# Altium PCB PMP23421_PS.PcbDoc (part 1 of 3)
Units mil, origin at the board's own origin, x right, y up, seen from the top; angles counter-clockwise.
Board outline 1978.53 x 2528.22 mil, 6 copper layers (Top Layer, Signal Layer 1, Signal Layer 2, Signal Layer 3, Signal Layer 4, Bottom Layer), stack 61.3 mil thick; 156 components, 45 nets, 410 pads, 635 vias.
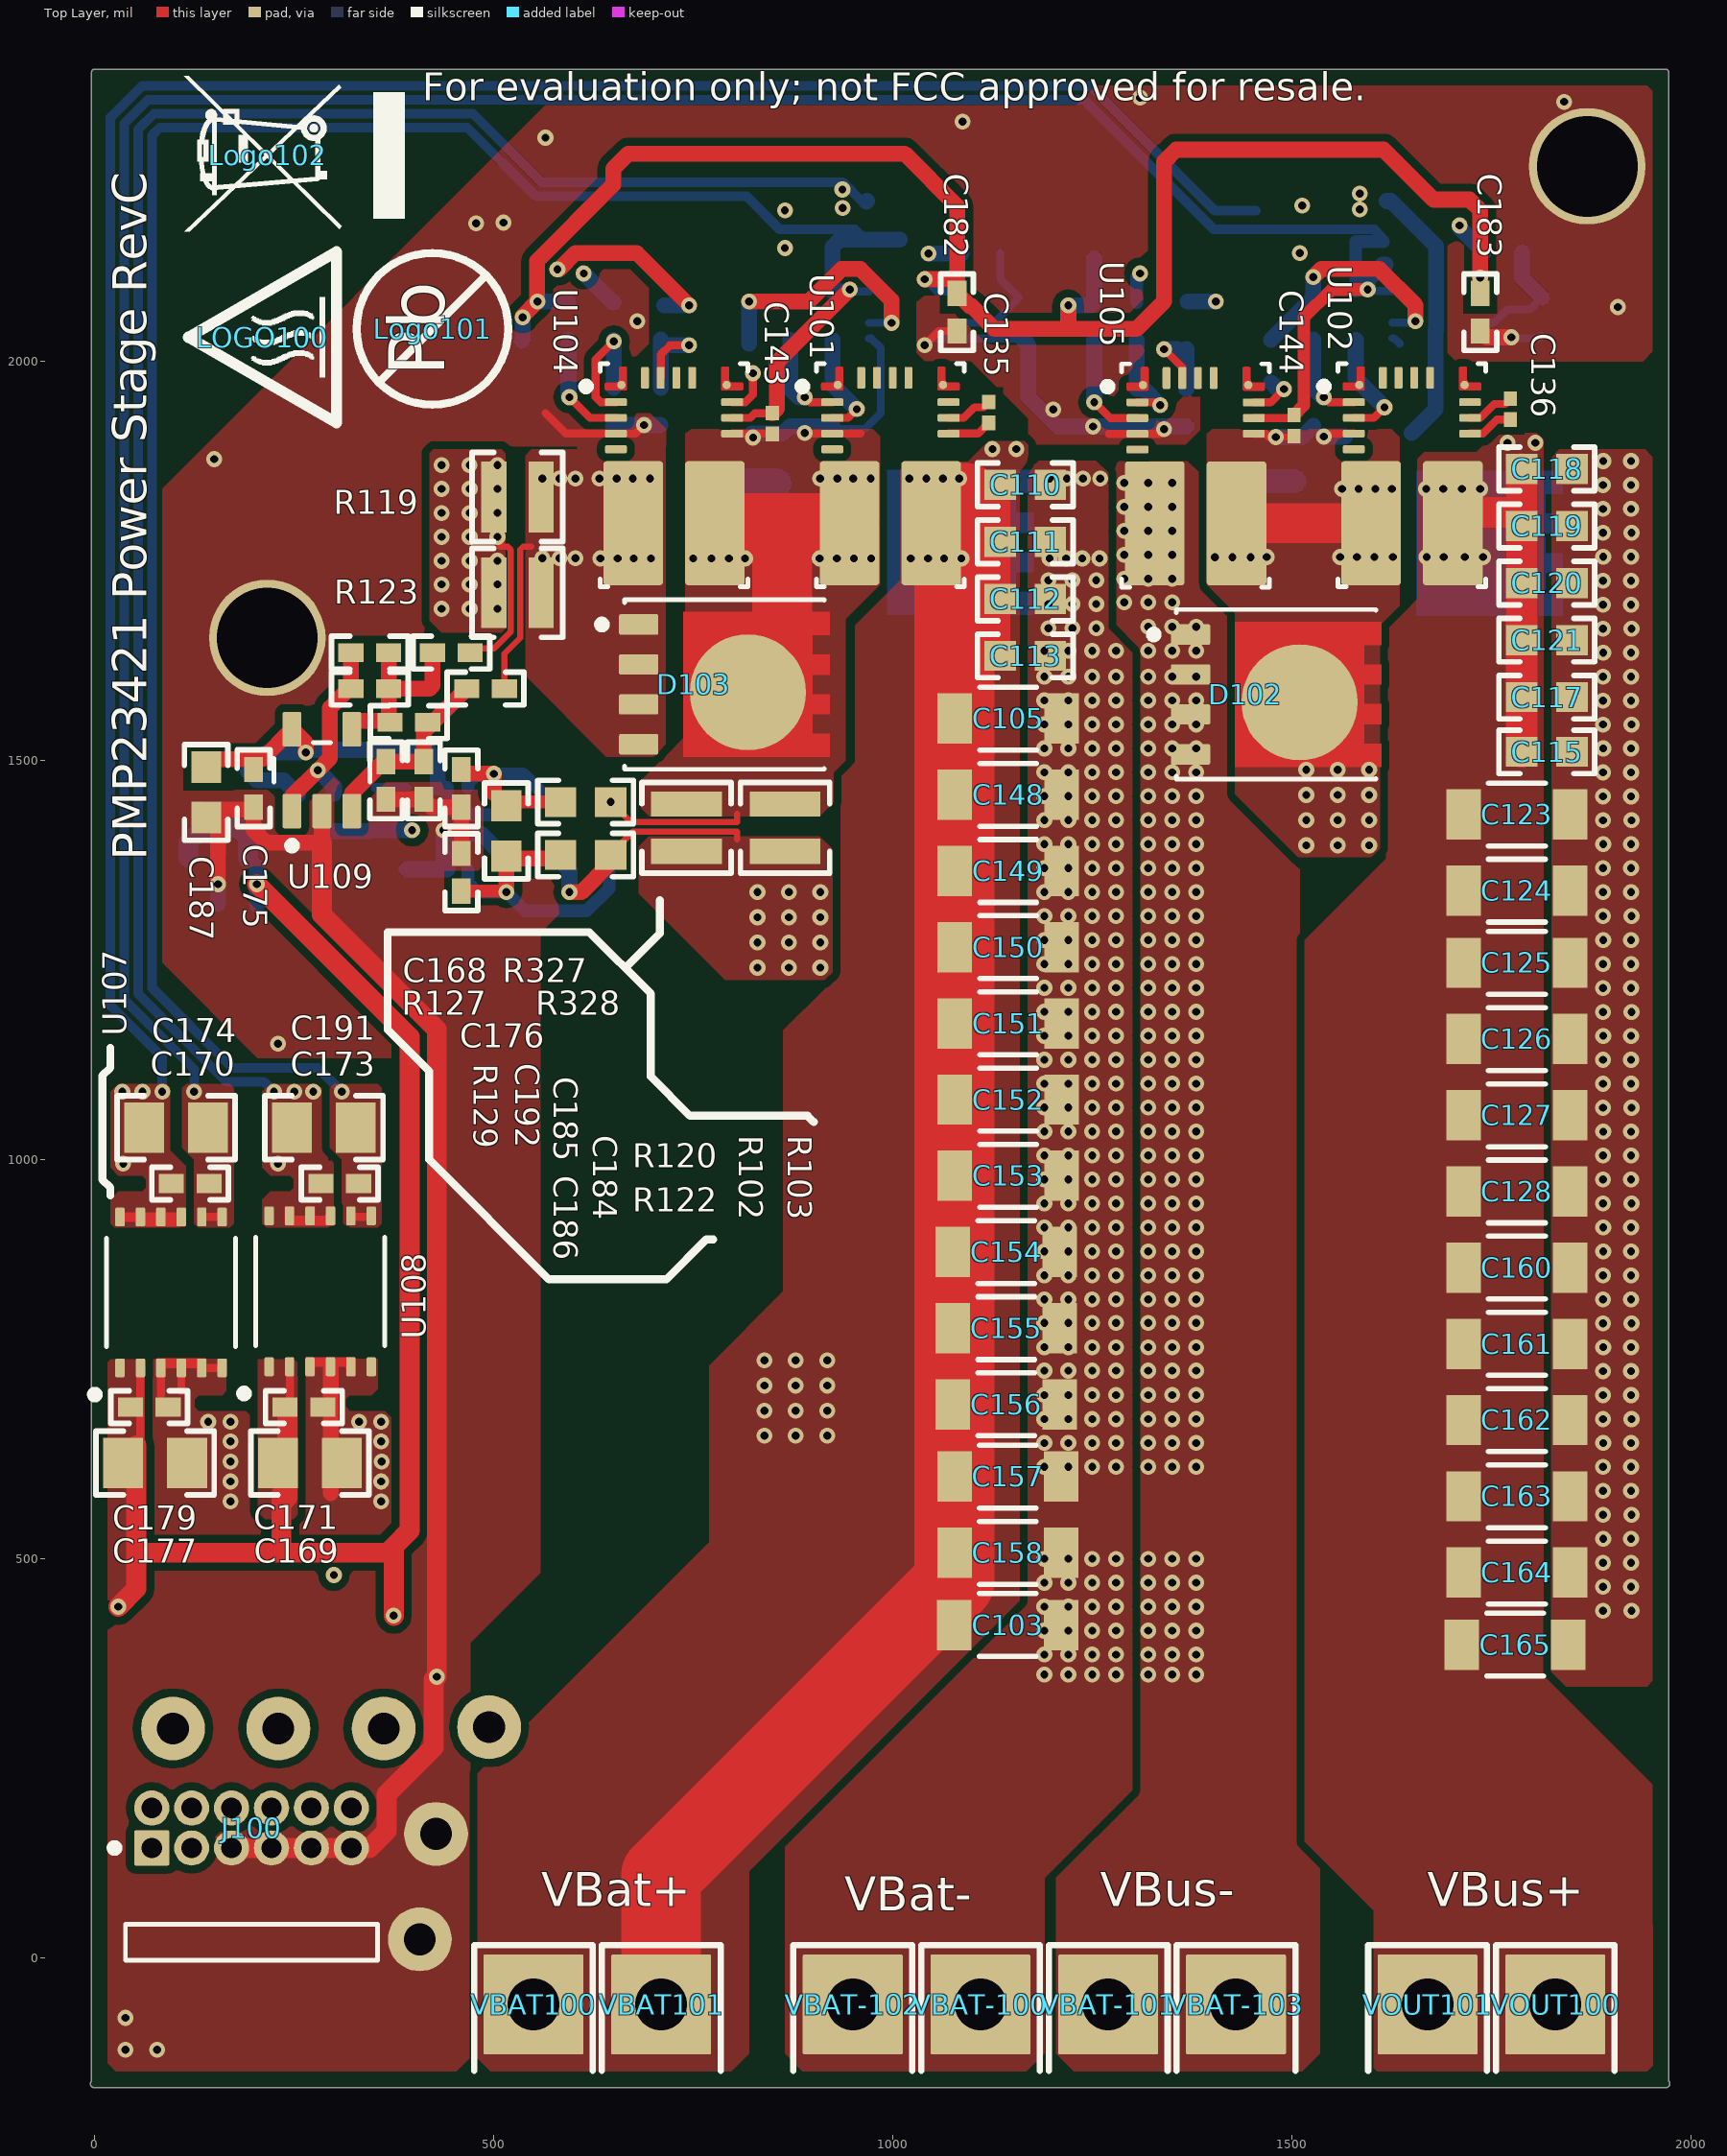
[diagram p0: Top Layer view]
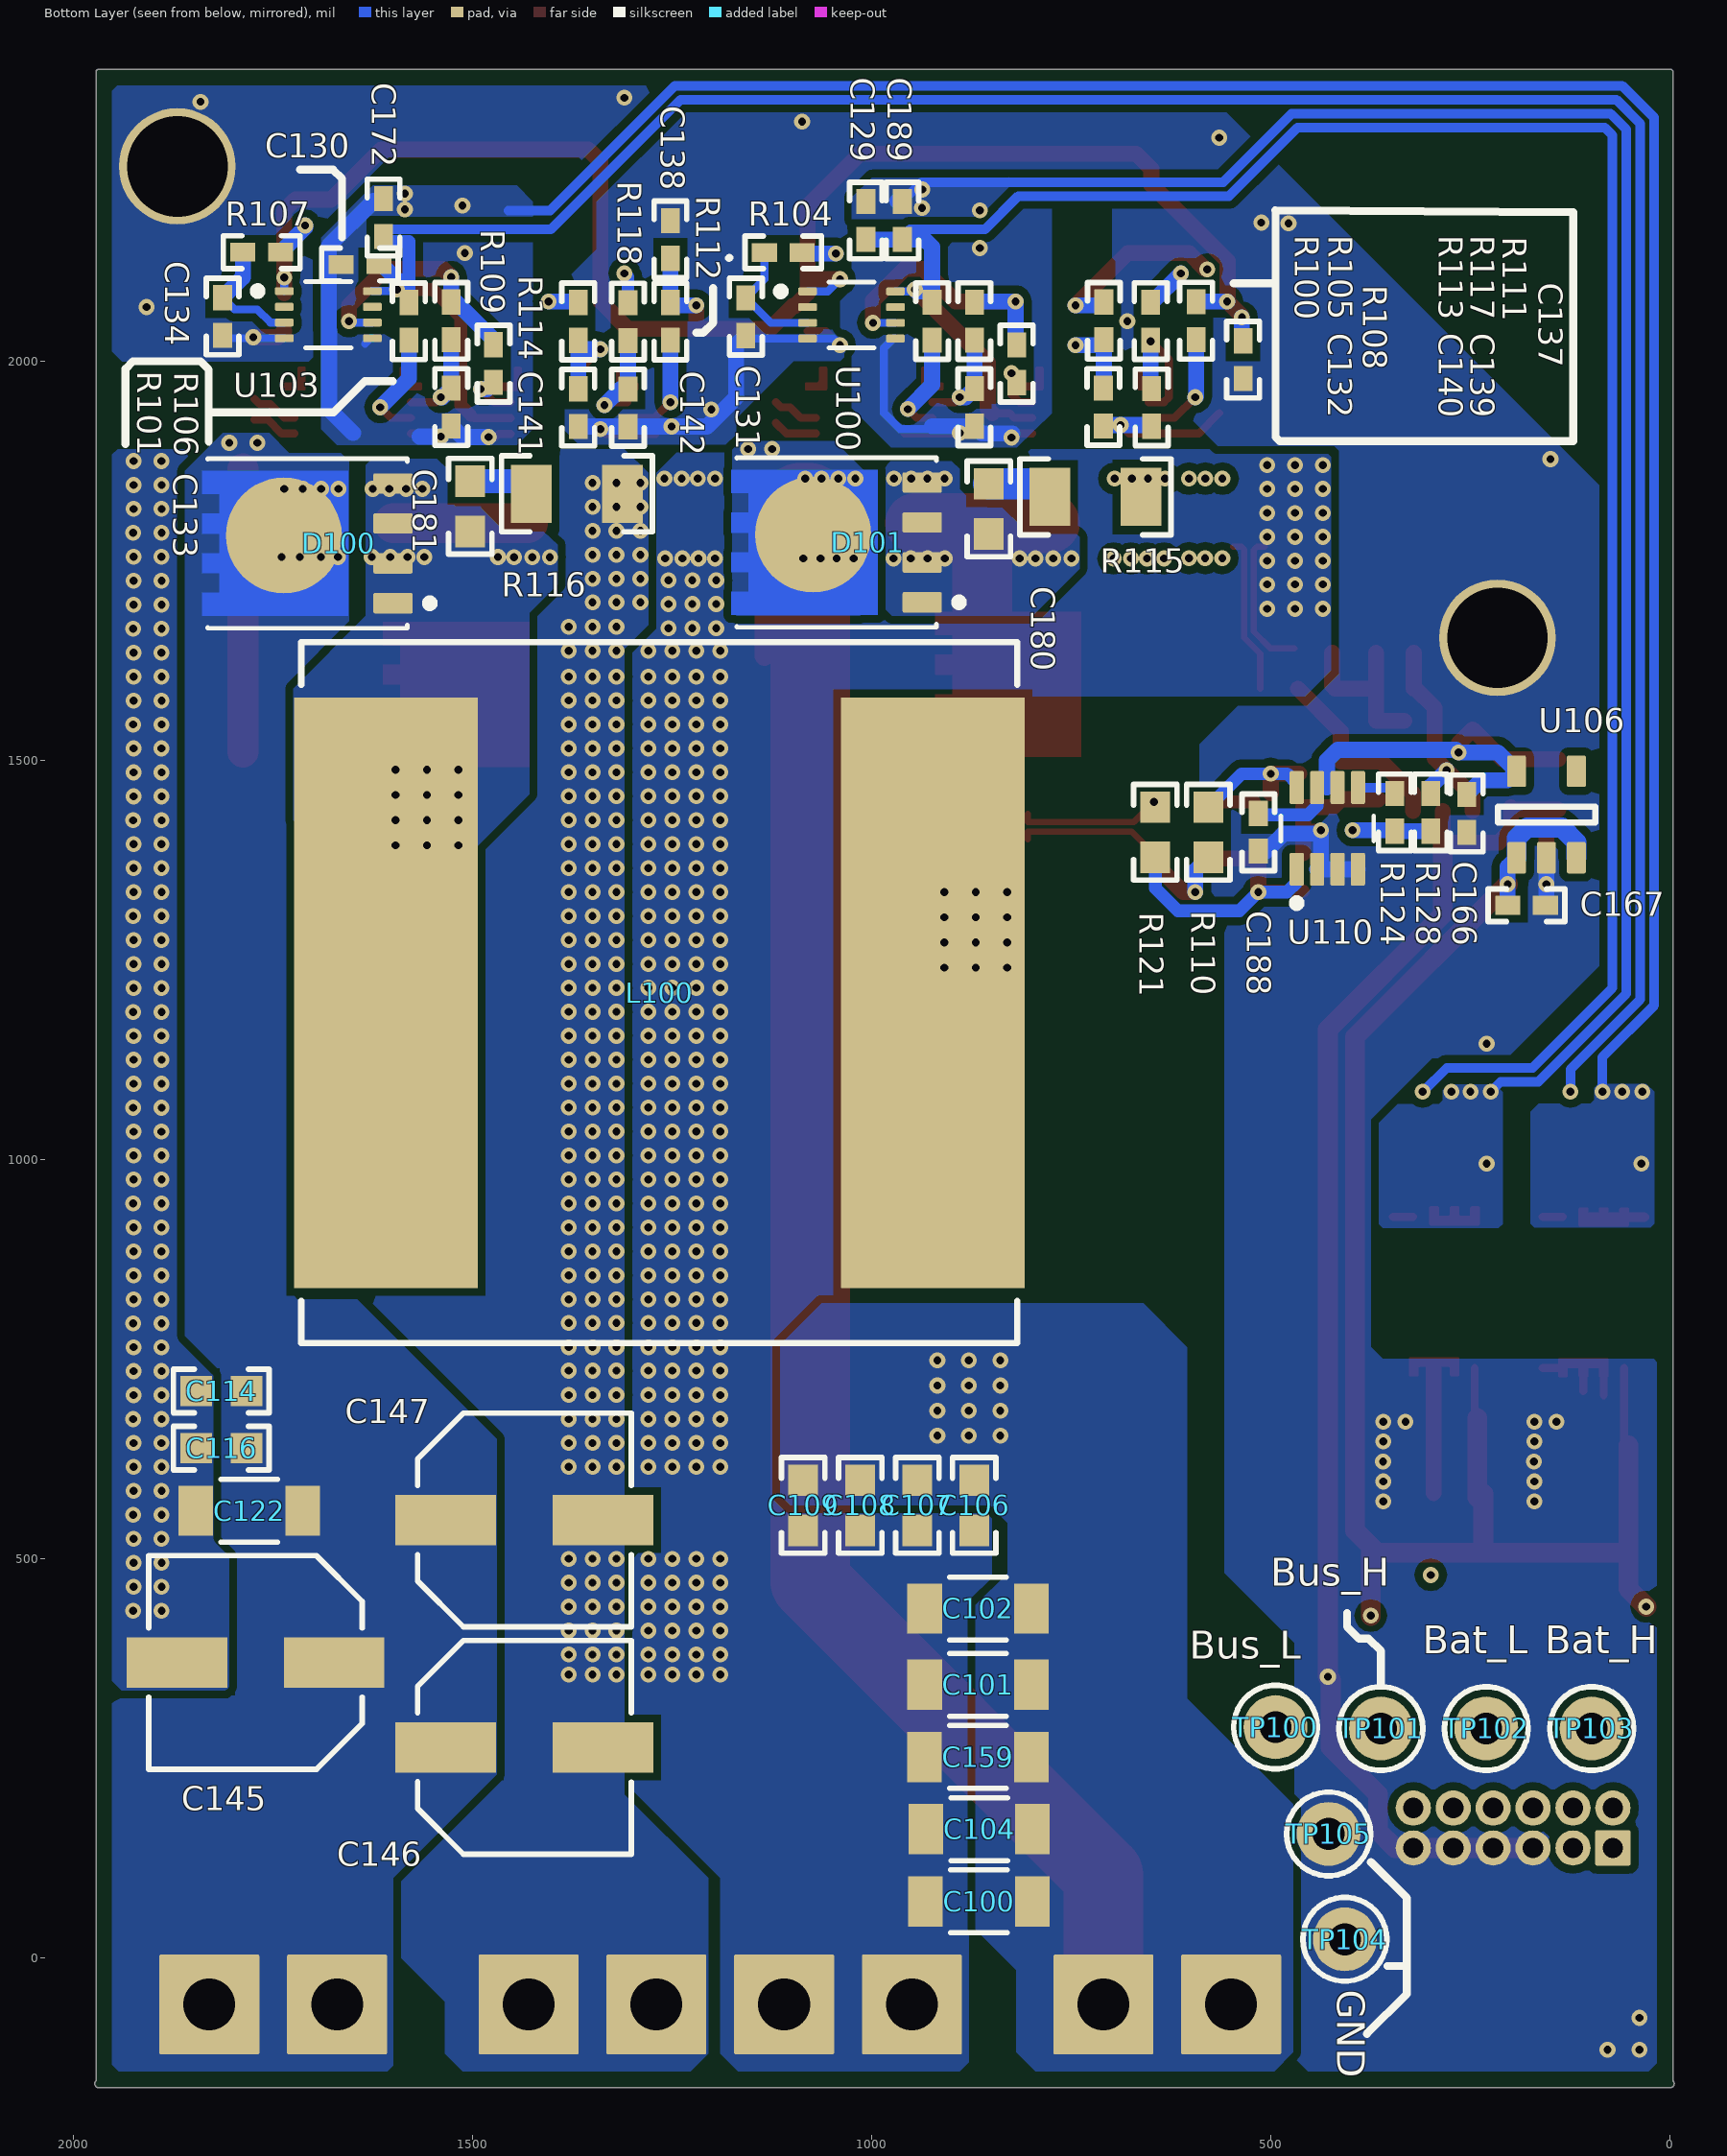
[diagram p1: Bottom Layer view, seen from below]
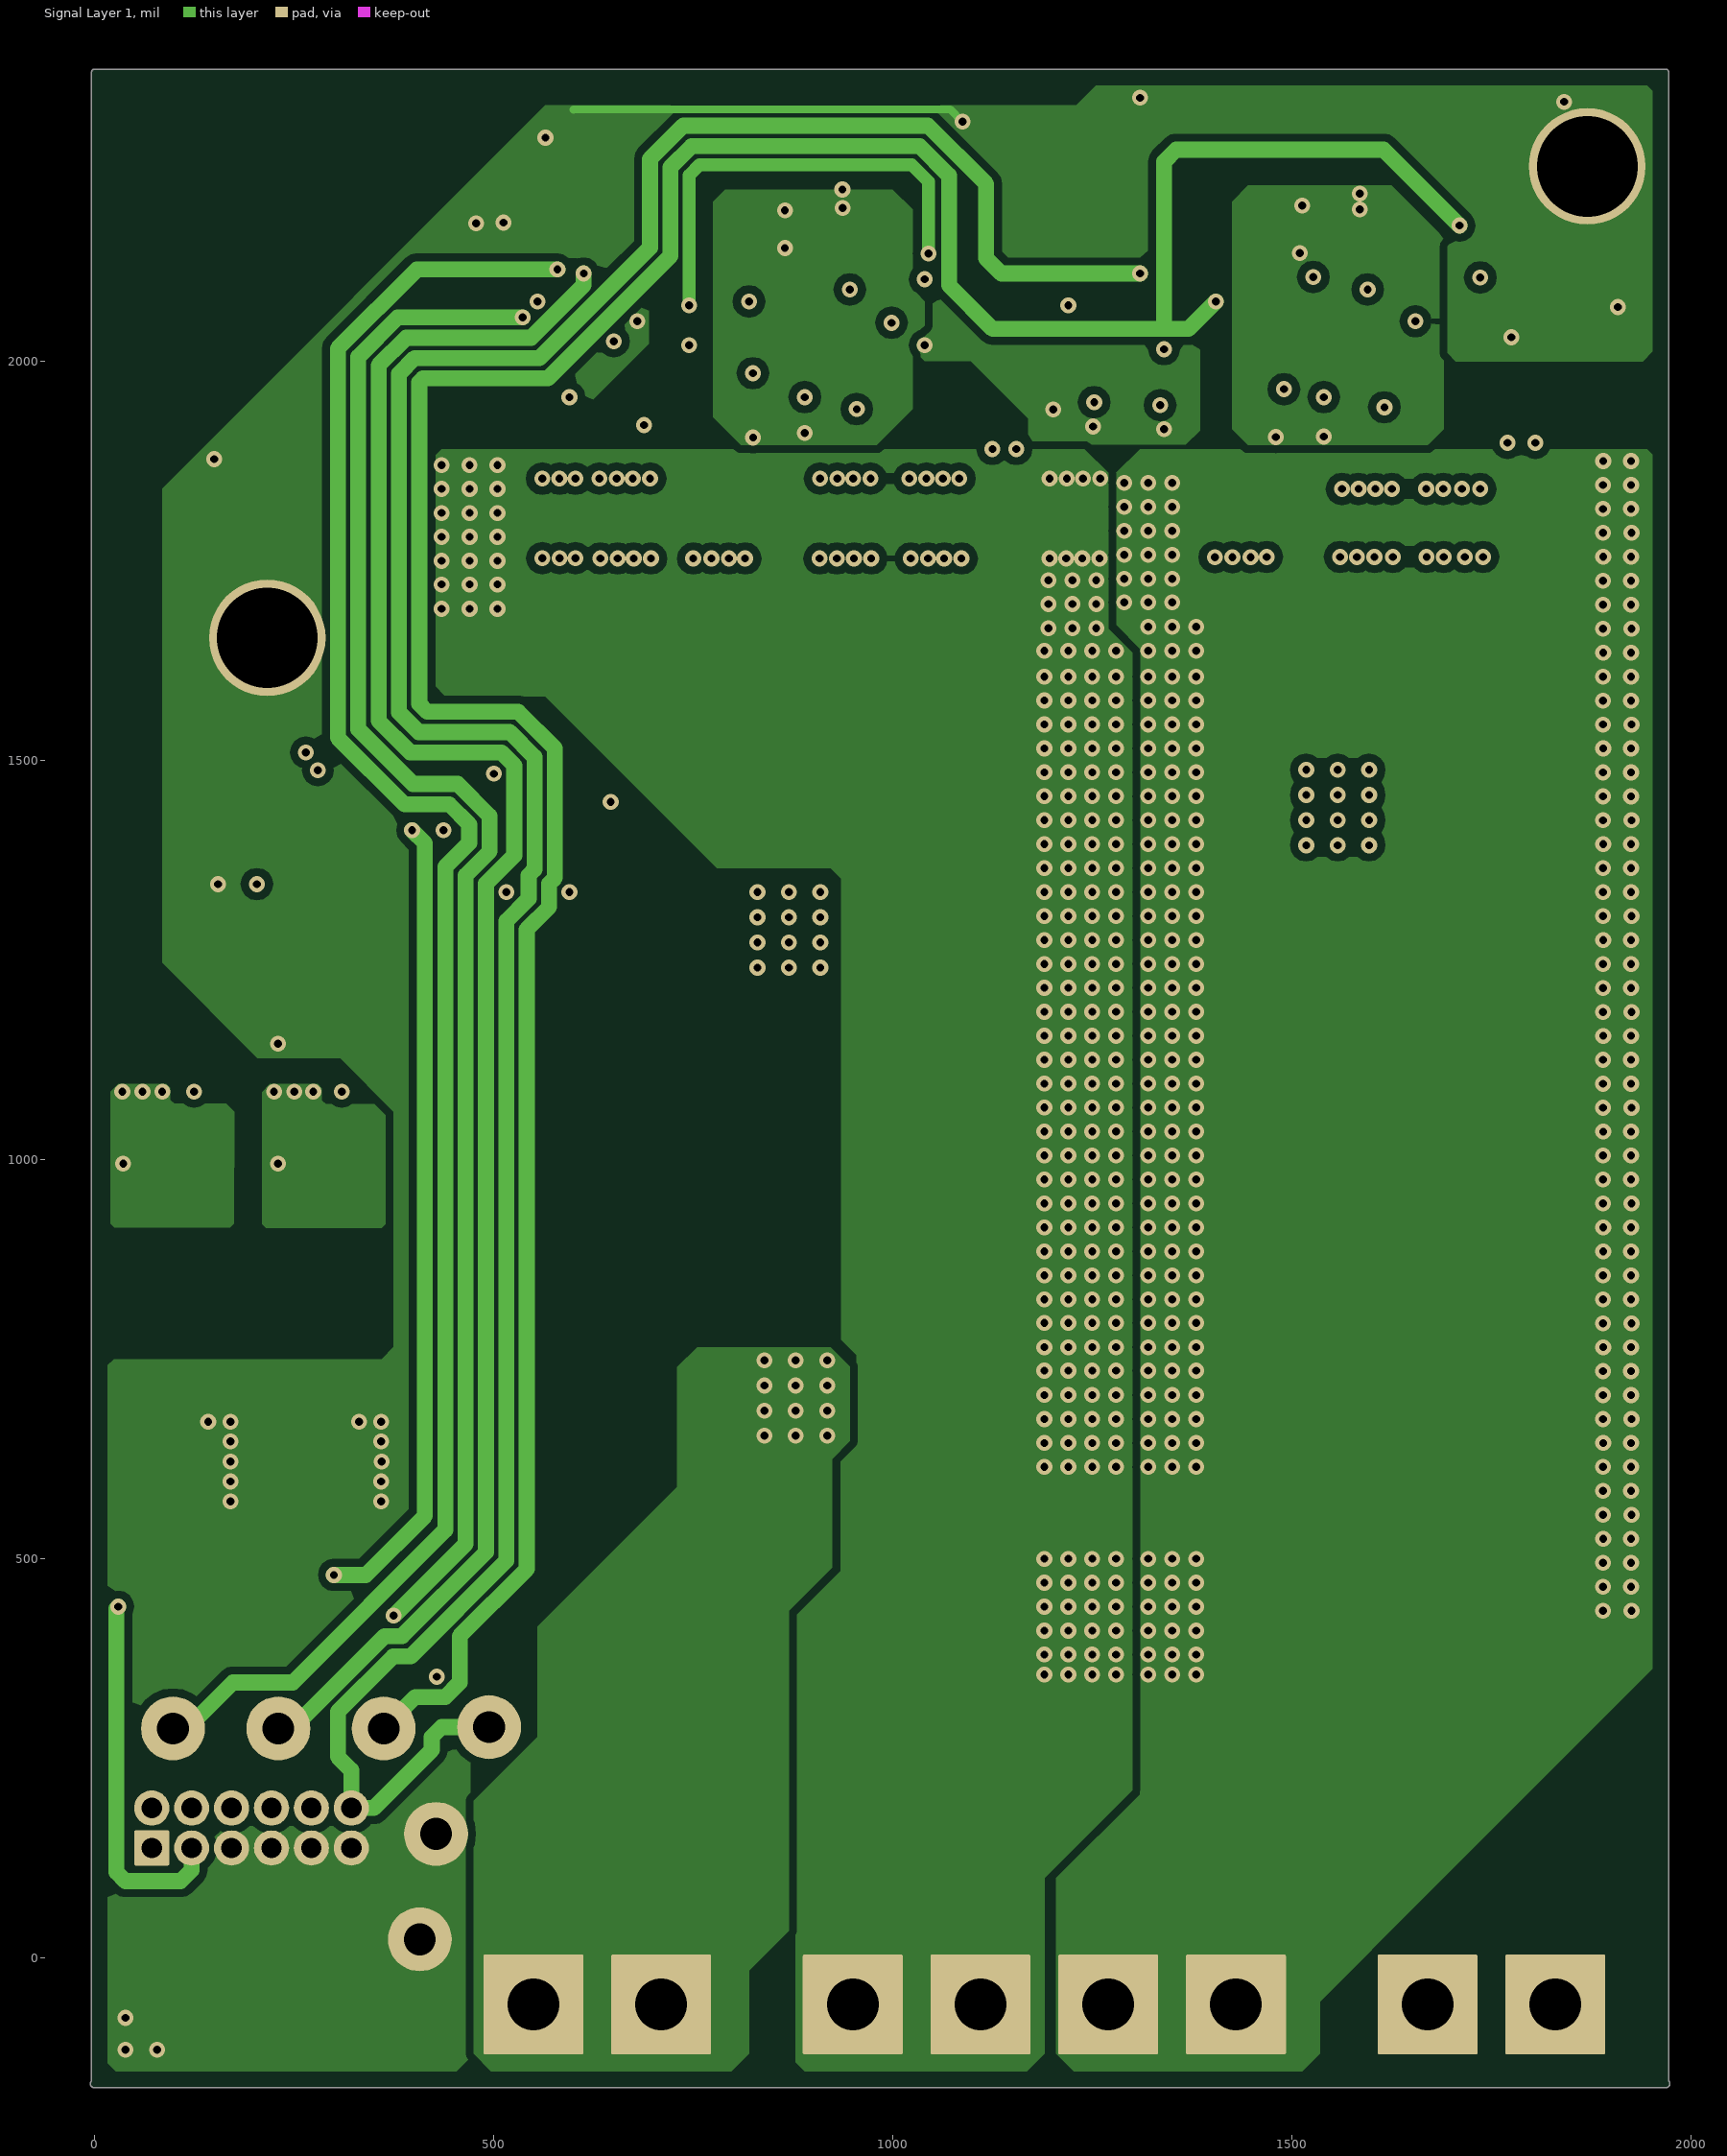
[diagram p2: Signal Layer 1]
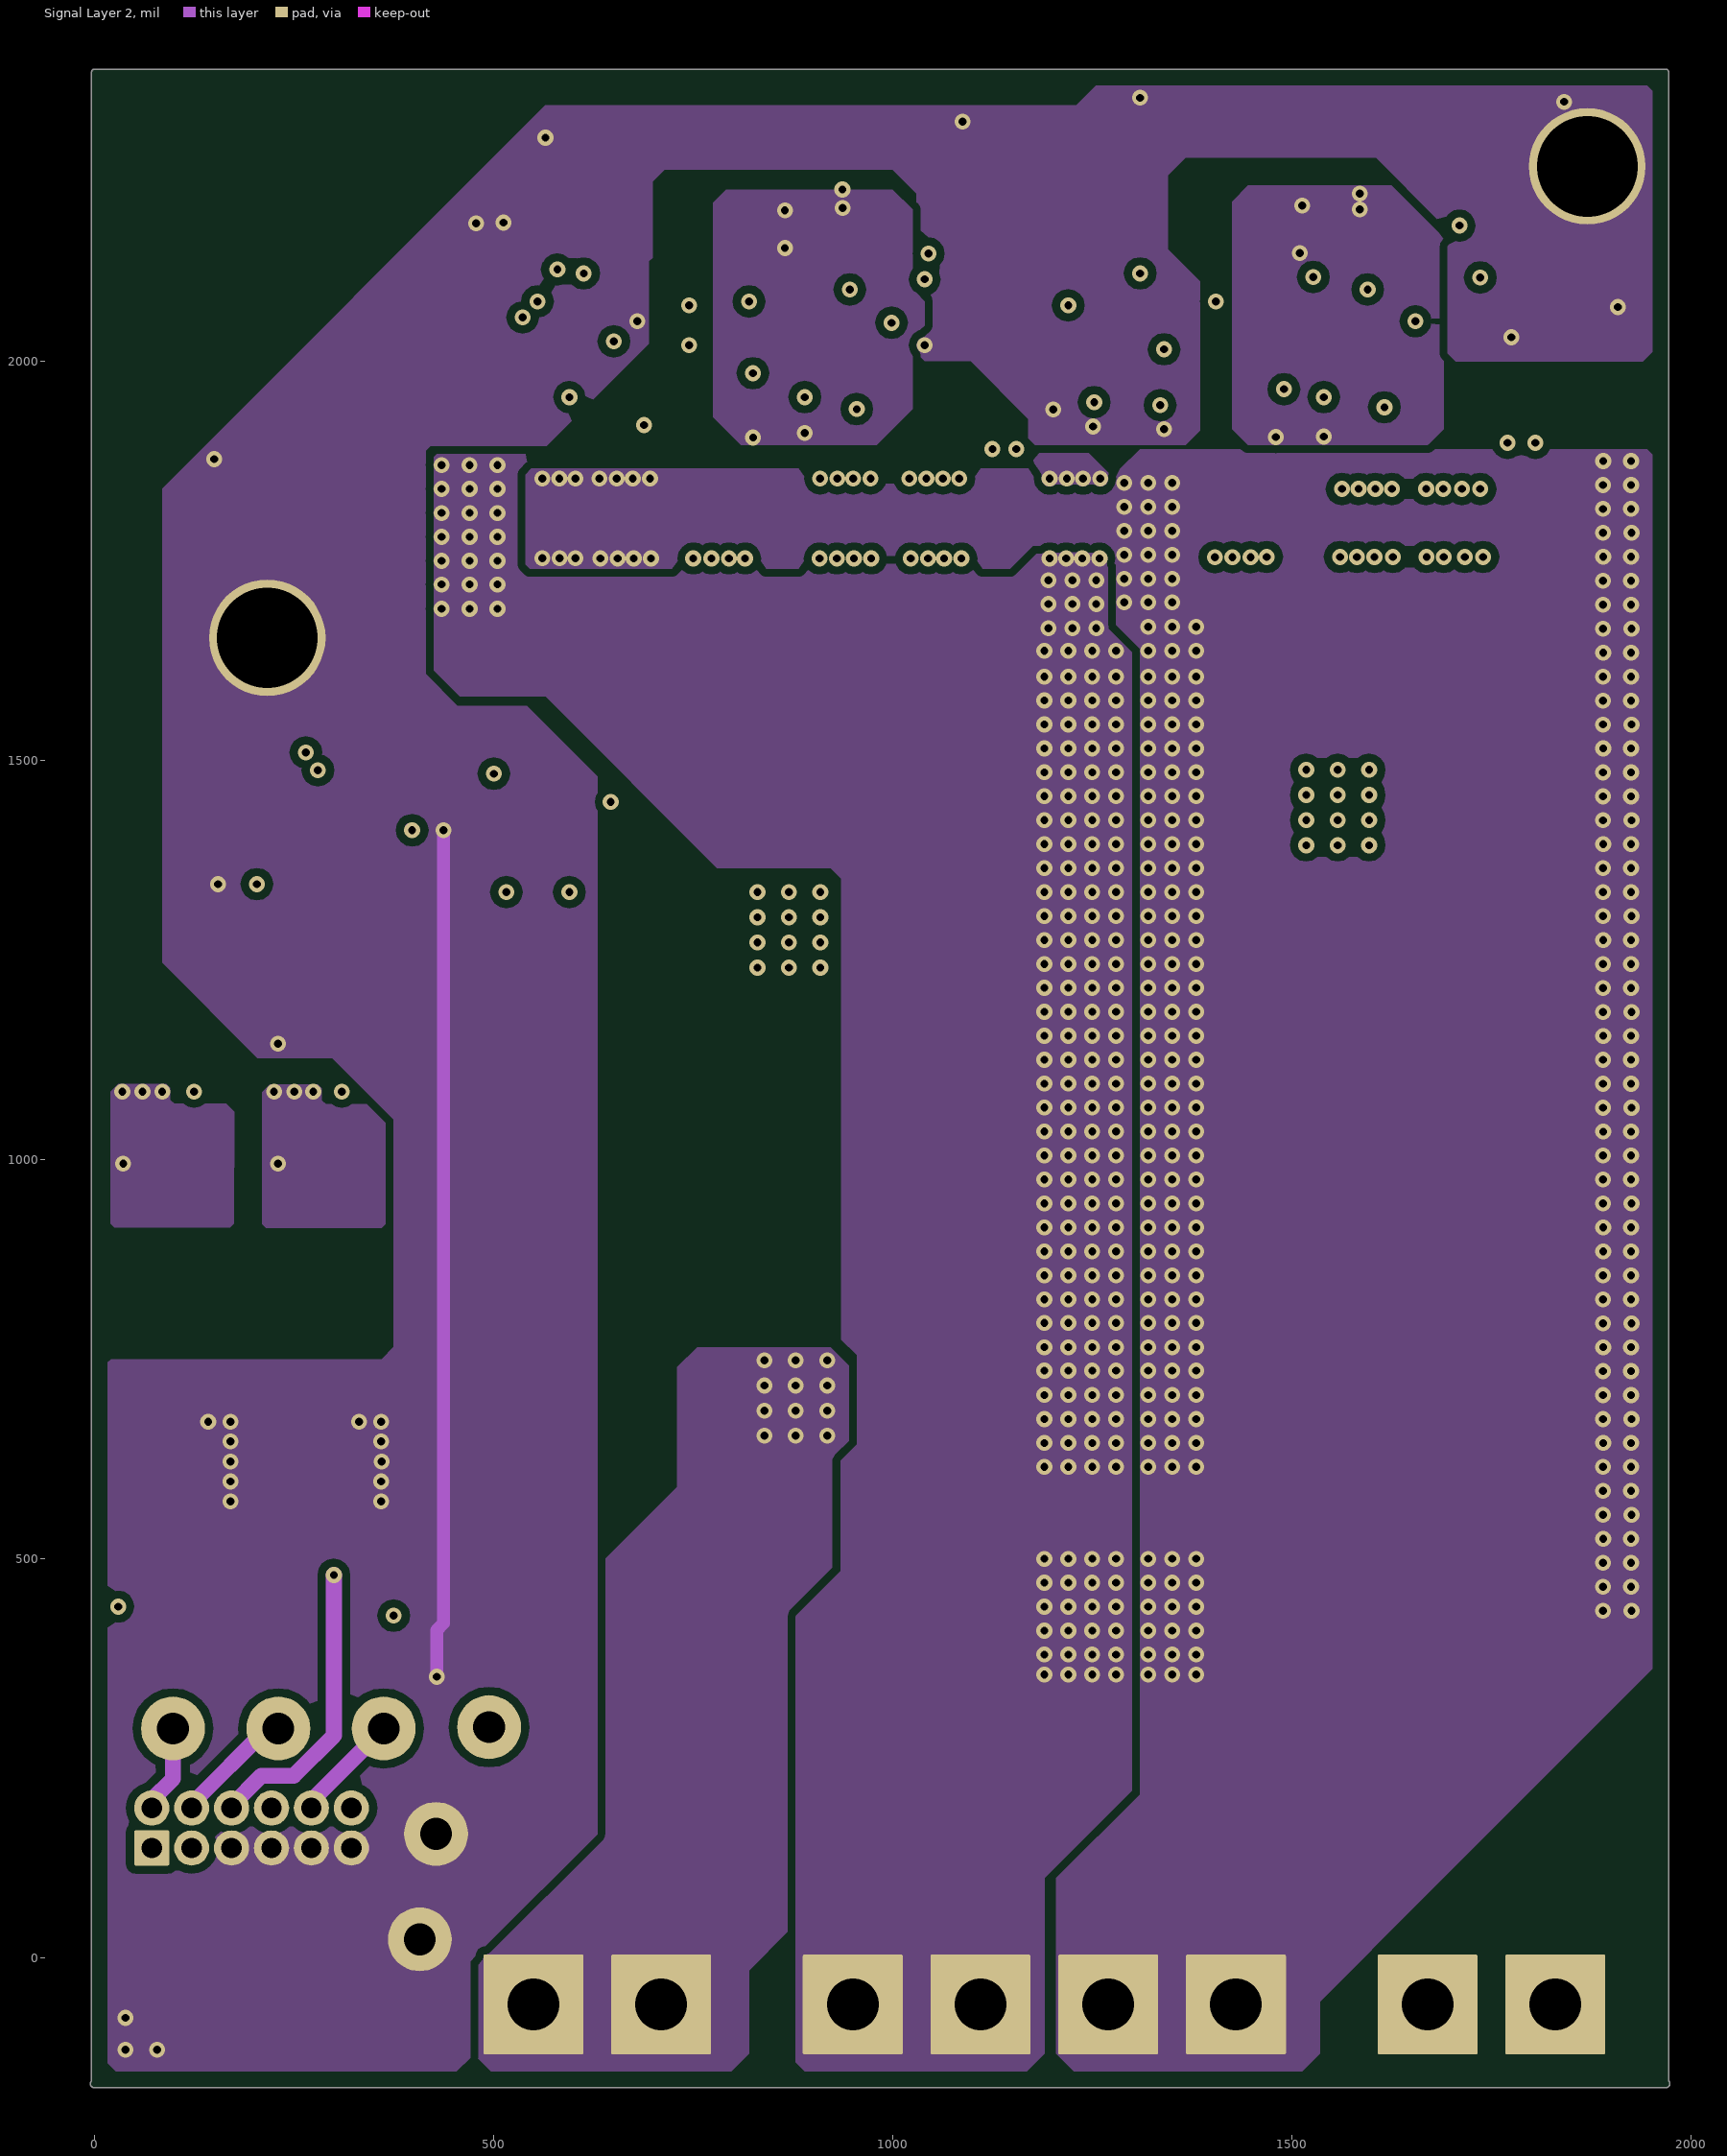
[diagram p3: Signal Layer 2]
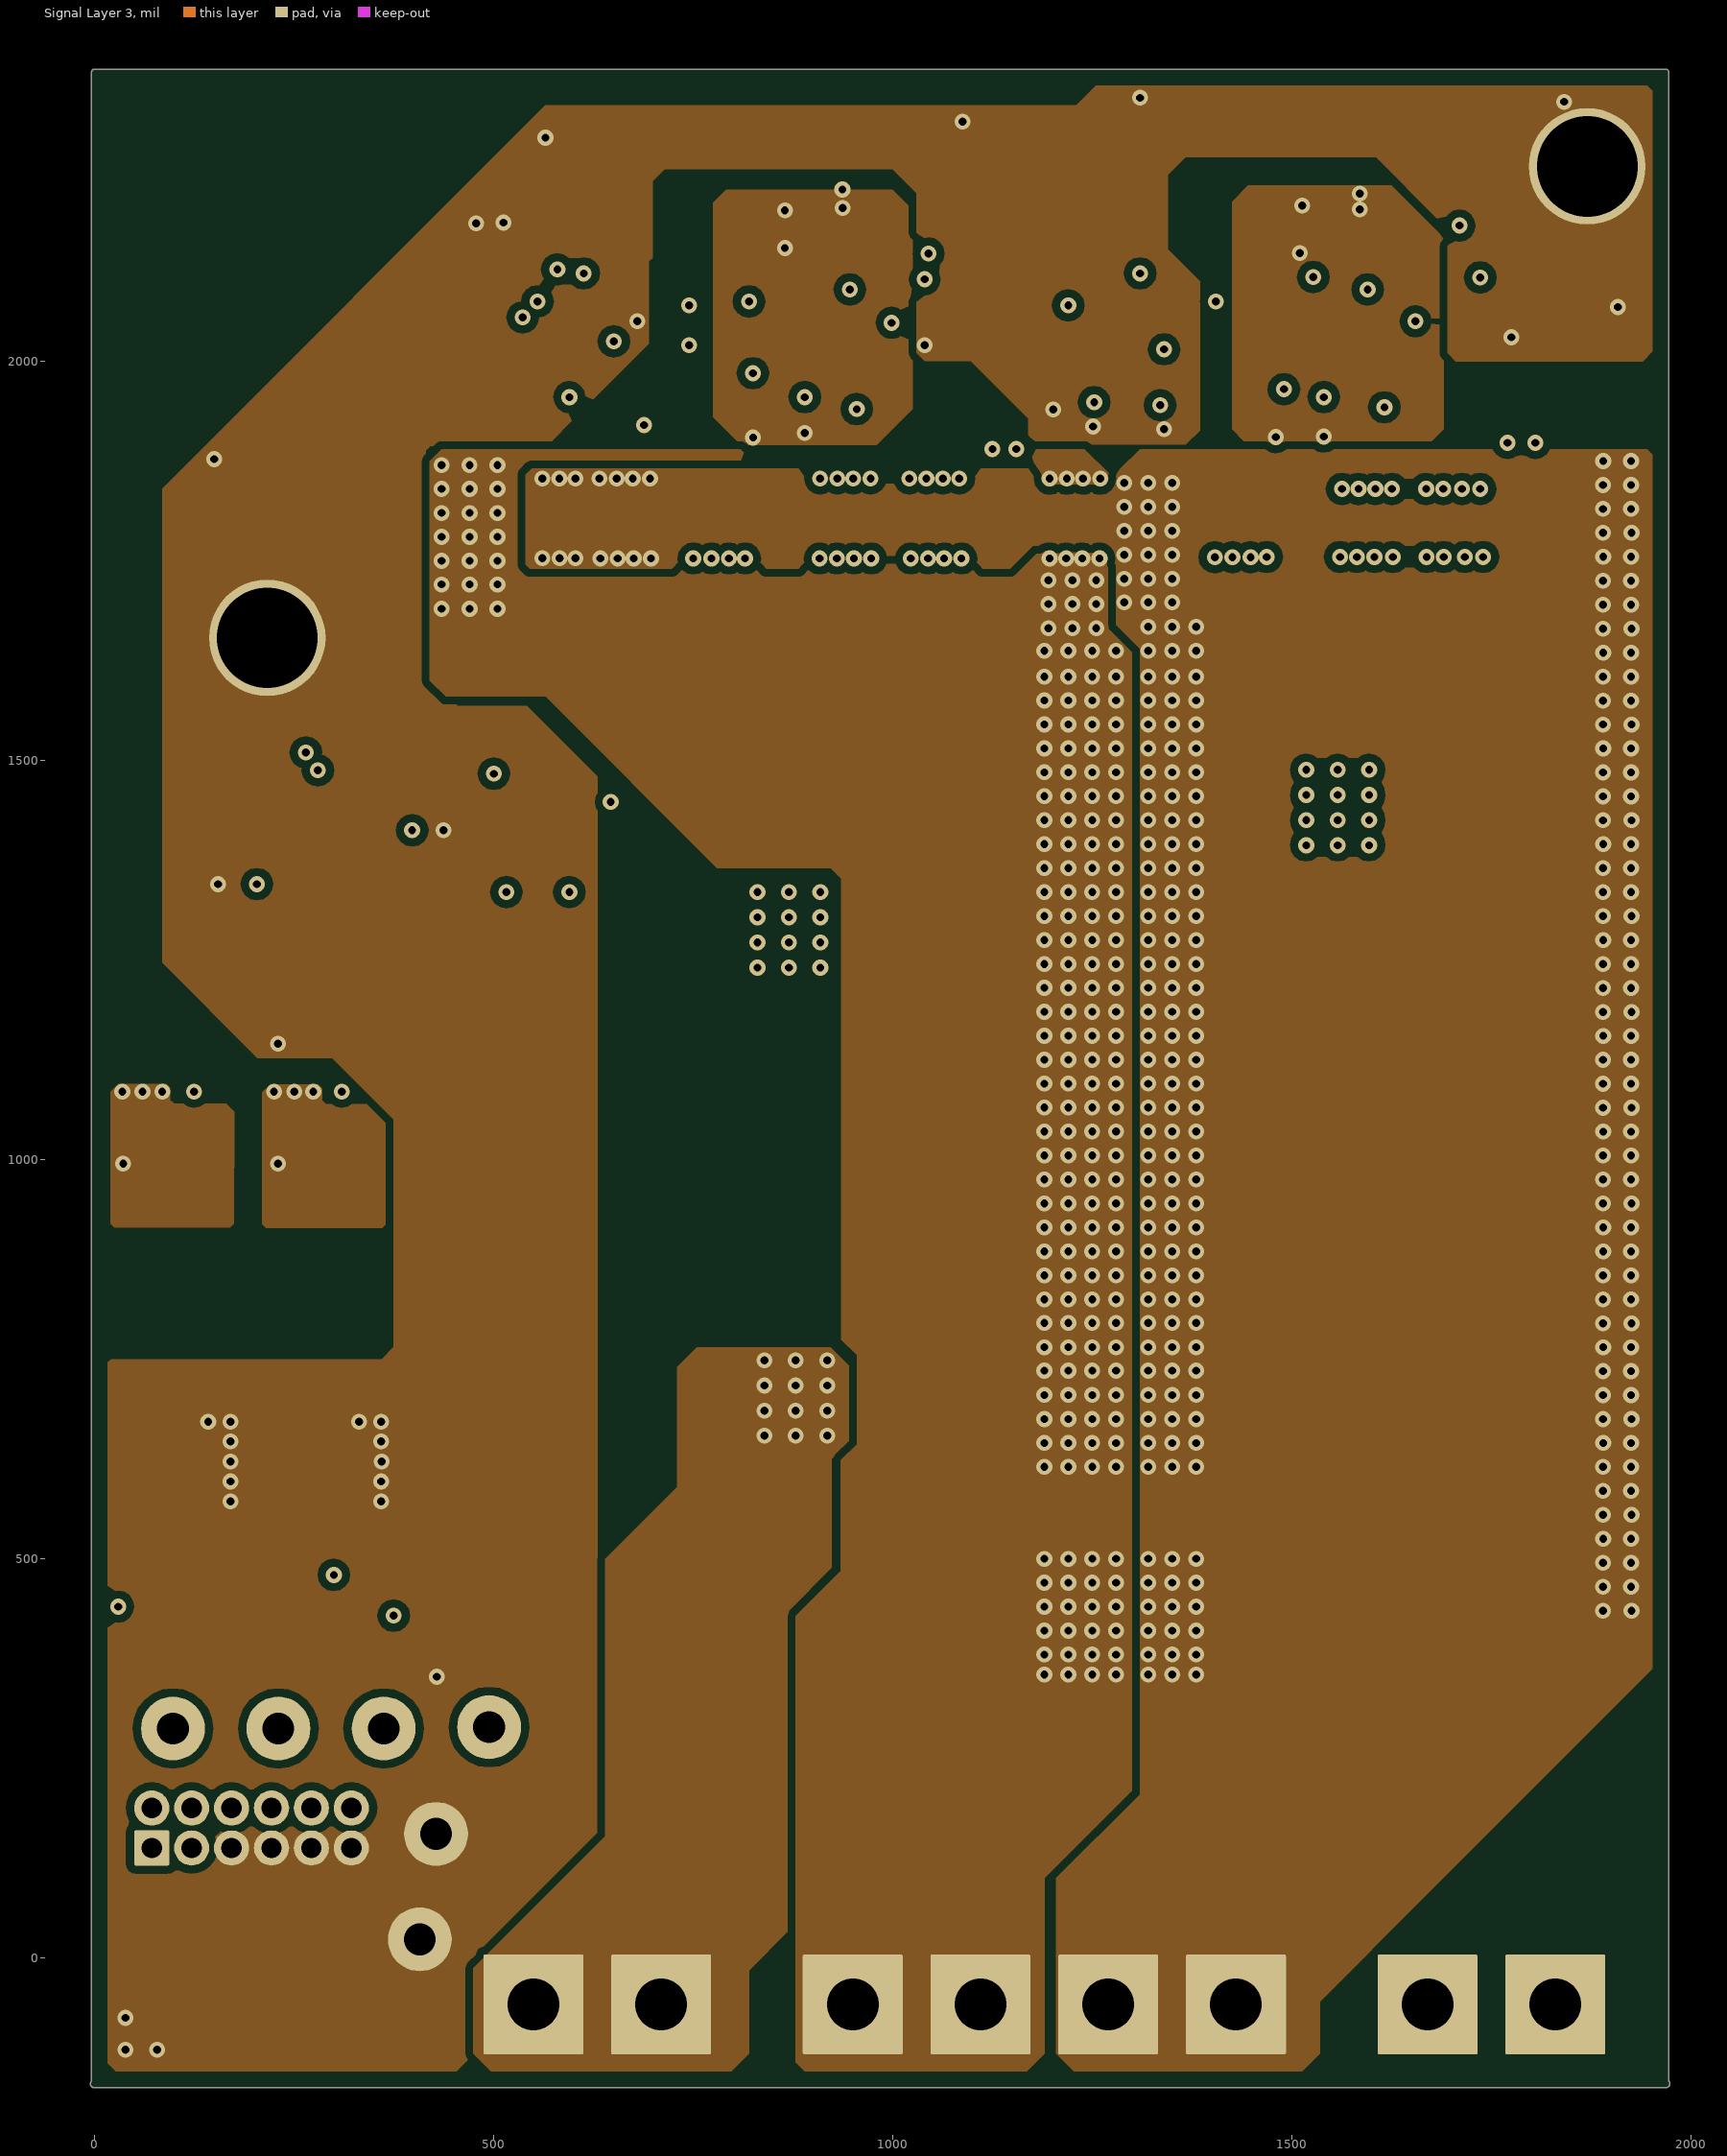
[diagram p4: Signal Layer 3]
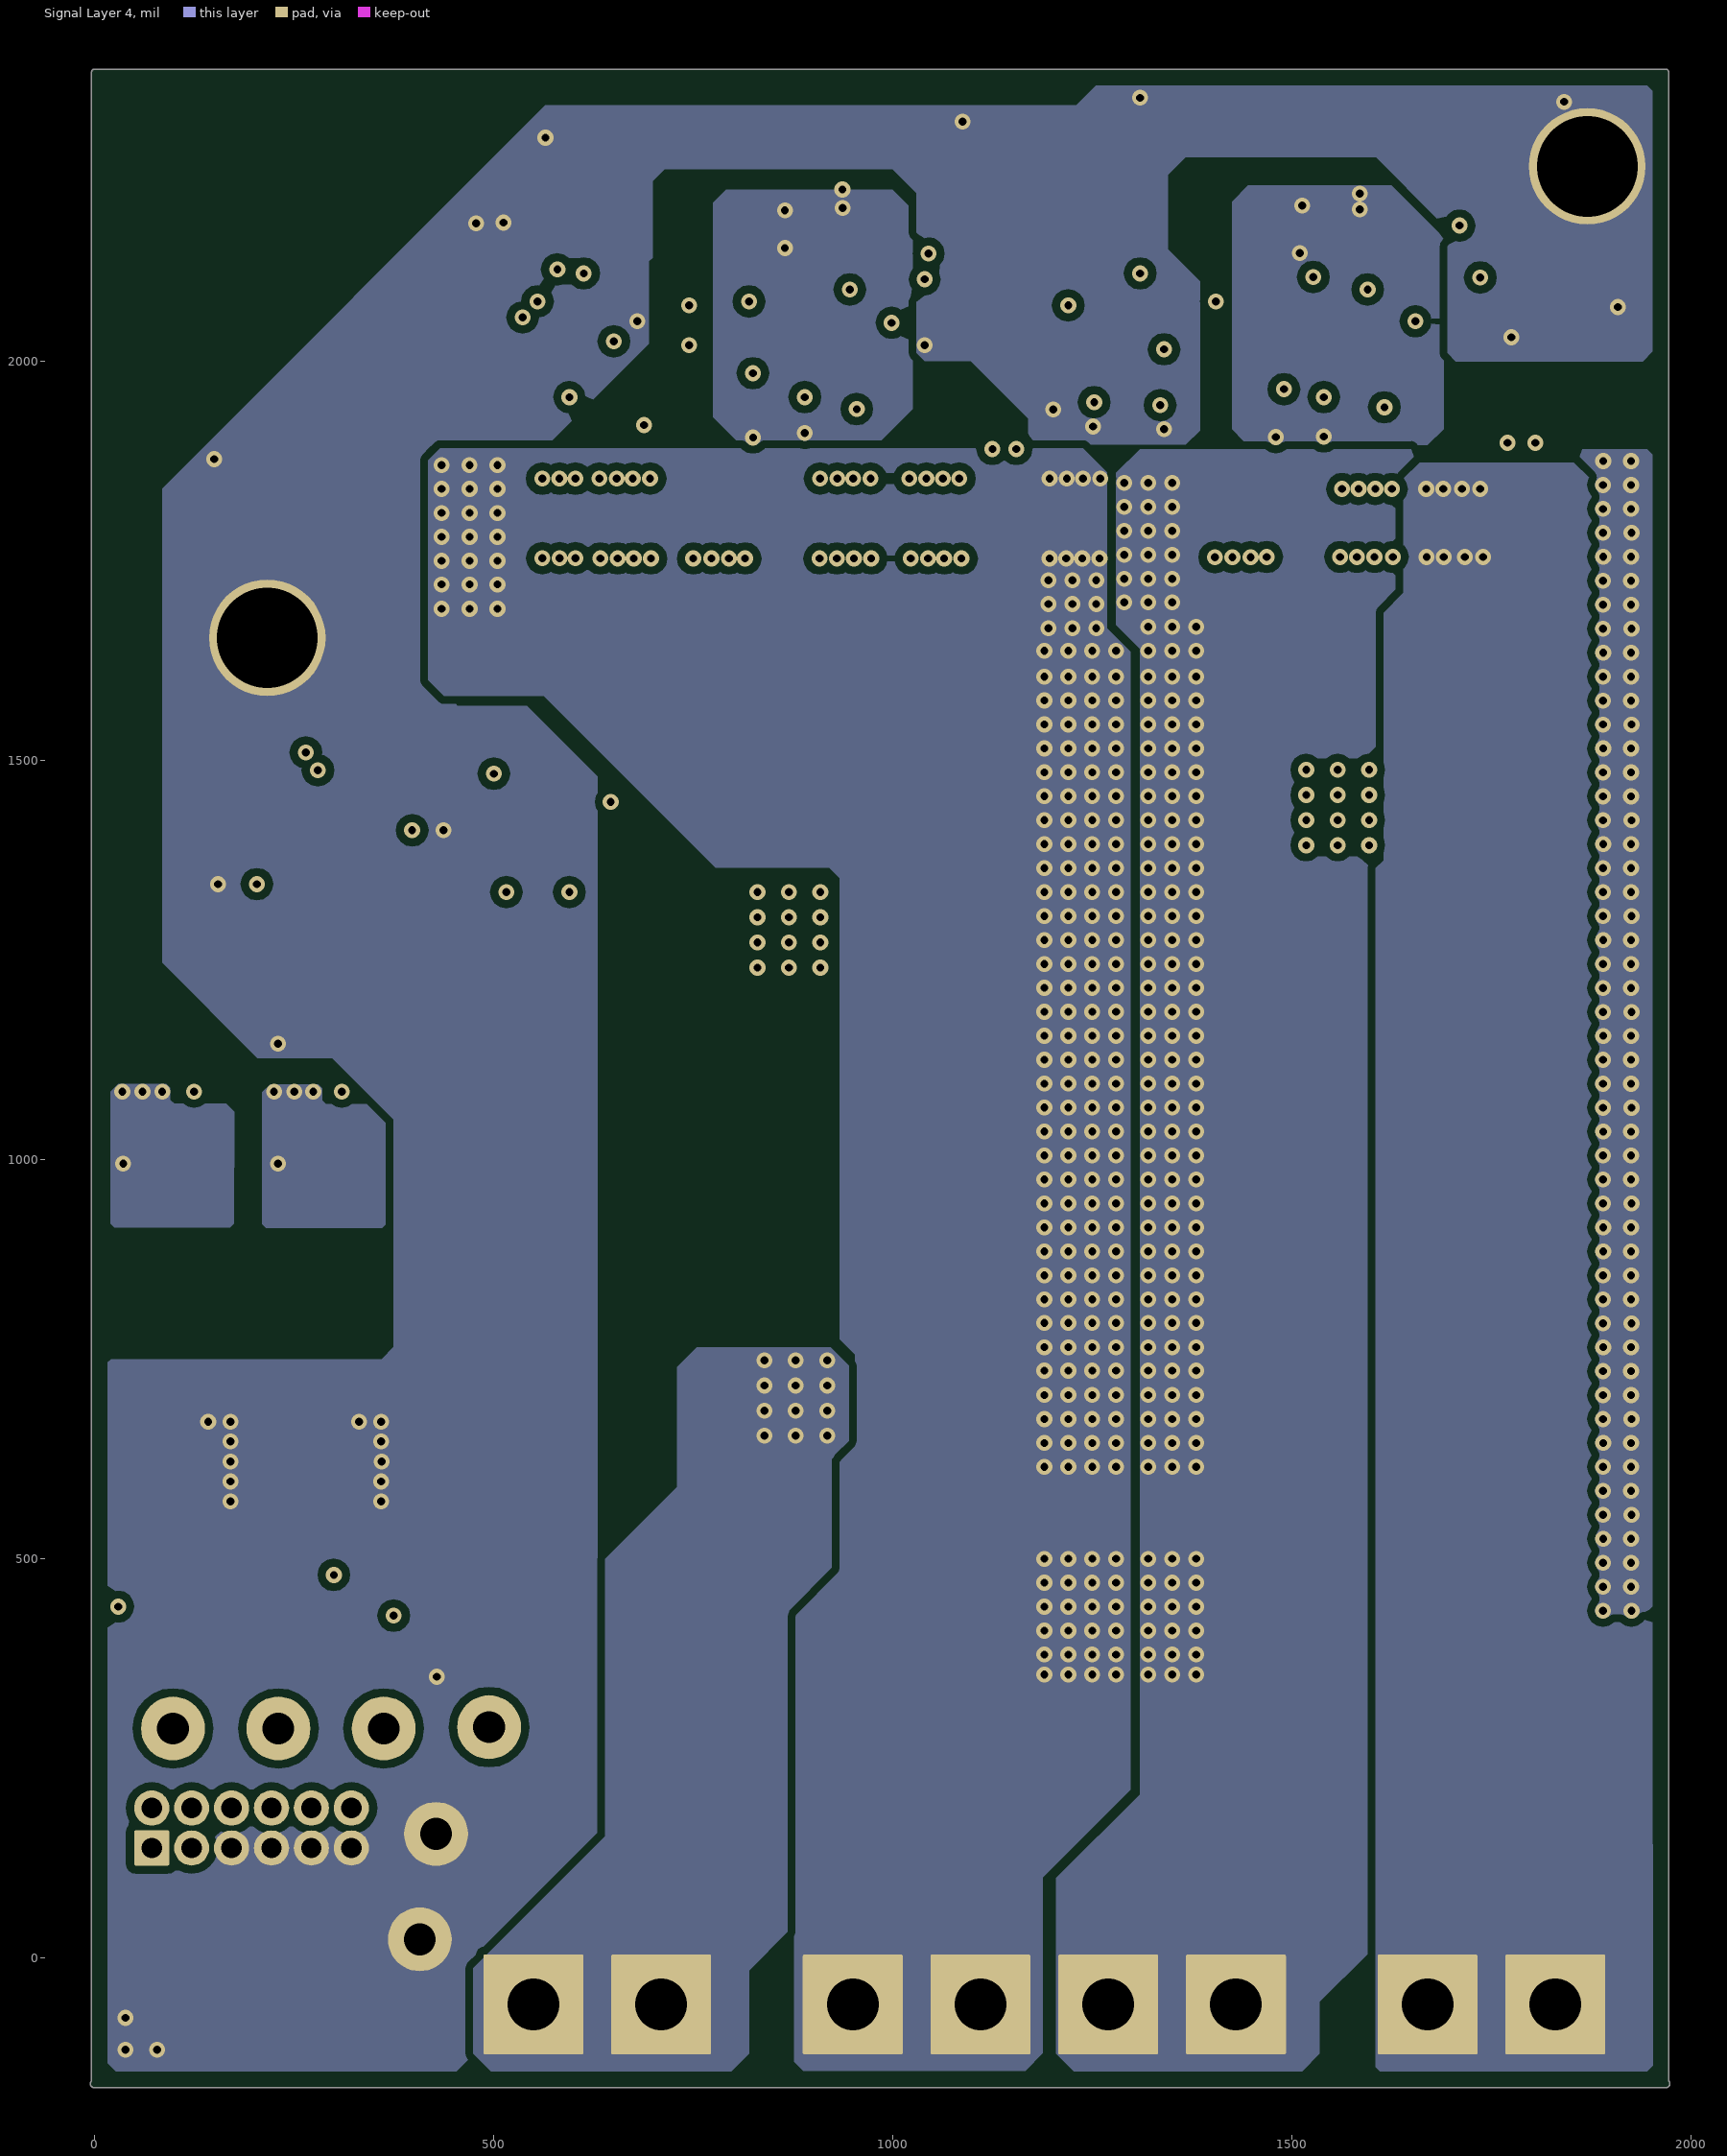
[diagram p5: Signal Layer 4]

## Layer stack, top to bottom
Top Solder: solder mask 0.394, Solder Resist, Dk 3.5
Top Layer: signal copper 2.8
Dielectric 2: prepreg 5.5, FR-4, Dk 4.2
Signal Layer 1: signal copper 2.8
Dielectric1: core 14, FR-4, Dk 4.2
Signal Layer 2: signal copper 2.8
Dielectric 3: prepreg 5.5, FR-4, Dk 4.2
Signal Layer 3: signal copper 2.8
Dielectric 4: dielectric 14, FR-4, Dk 4.2
Signal Layer 4: signal copper 2.8
Dielectric 5: dielectric 5.5, FR-4, Dk 4.2
Bottom Layer: signal copper 2.8
Bottom Solder: solder mask 0.394, Solder Resist, Dk 3.5

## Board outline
0,-162.5 cw(c0,-157.48) -3.52,-153.91 -3.52,2362.2 cw(c0,2362.2) 0,2365.72 1968.5,2365.72 cw(c1968.5,2362.2) 1972.02,2362.2 1972.02,-153.91 cw(c1968.5,-157.48) 1973.52,-157.48 cw(c1968.5,-157.48) 1968.5,-162.5

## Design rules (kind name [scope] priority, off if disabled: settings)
AcuteAngle [All] p1: minimum=1.50000000000000E+0001 checktracksonly=FALSE
AssemblyTestPointUsage [All] p1: valid=2
BoardOutlineClearance BoardOutlineClearance_MountingHoles [OnCopper and InComponentClass('Mounting Holes')] p1: gap=40 ignorepadtopadclearanceinfootprint=FALSE
BoardOutlineClearance BoardOutlineClearance_Poly [OnCopper and IsPoly] p2: gap=20 ignorepadtopadclearanceinfootprint=FALSE
BoardOutlineClearance [OnCopper and Not InComponentClass('Logo') and not InComponentClass('FiducialMark') and not InRegion(1000,500,4000,800) and not InPoly] p3: gap=10 ignorepadtopadclearanceinfootprint=FALSE
Clearance Clearance_1 [InNetClass('HV') vs Not InNetClass('HV')] p1: gap=20 ignorepadtopadclearanceinfootprint=FALSE
Clearance Clearance_Keepouts [((IsTrack Or IsArc) And Not InPoly) And IsFree and IsKeepOut vs ((IsTrack Or IsArc) And Not InPoly) And IsFree and IsKeepOut] p2: gap=0 ignorepadtopadclearanceinfootprint=FALSE
Clearance Clearance_Poly [InPolygon] p3: gap=10 ignorepadtopadclearanceinfootprint=FALSE
Clearance Clearance_FiducialMark [IsKeepOut and InComponentClass('FiducialMark') vs IsPad and InComponentClass('FiducialMark')] p4: gap=0 ignorepadtopadclearanceinfootprint=FALSE
Clearance [All] p5: gap=5.5 ignorepadtopadclearanceinfootprint=FALSE
ComponentClearance ComponentClearance_MountingHoles_FiducialMarks [InComponentClass('Mounting Holes') vs InComponentClass('FiducialMark')] p1: gap=50 collisioncheckmode=3 verticalgap=10 showdistances=FALSE
ComponentClearance ComponentClearance_Shunt [InComponentClass('Header') vs InComponentClass('Shunt')] p2: gap=0 collisioncheckmode=3 verticalgap=0 showdistances=FALSE
ComponentClearance ComponentClearance_Logo [InComponentClass('Logo')] p3: gap=50 collisioncheckmode=3 verticalgap=10 showdistances=FALSE
ComponentClearance ComponentClearance_ScrewToNut [(HasFootprint('NY PMS 440 0025 PH')) vs (HasFootprint('Keystone_1902C'))] p4: gap=5 collisioncheckmode=3 verticalgap=10 showdistances=FALSE
ComponentClearance ComponentClearance_MountingHoles [InComponentClass('Mounting Holes')] p5: gap=250 collisioncheckmode=3 verticalgap=100000 showdistances=FALSE
ComponentClearance ComponentClearance_SmallPassives [HasFootprint('0201*') or HasFootprint('0402*') or HasFootprint('0508') or HasFootprint('0603*') or HasFootprint('0612') or HasFootprint('0805*') or HasFootprint('0815*') or HasFootprint('0830*') or HasFootprint('1206*') or HasFootprint('1210*') or HasFootprint('1808*') or HasFootprint('1812*') or HasFootprint('1825*') or HasFootprint('2010*') or HasFootprint('2220*') or HasFootprint('2225*') or HasFootprint('2512*') or HasFootprint('2728*') or HasFootprint('3518*') vs HasFootprint('0201*') or HasFootprint('0402*') or HasFootprint('0508') or HasFootprint('0603*') or HasFootprint('0612') or HasFootprint('0805*') or HasFootprint('0815*') or HasFootprint('0830*') or HasFootprint('1206*') or HasFootprint('1210*') or HasFootprint('1808*') or HasFootprint('1812*') or HasFootprint('1825*') or HasFootprint('2010*') or HasFootprint('2220*') or HasFootprint('2225*') or HasFootprint('2512*') or HasFootprint('2728*') or HasFootprint('3518*')] p6: gap=5 collisioncheckmode=3 verticalgap=5 showdistances=FALSE
ComponentClearance ComponentClearance_THtoSMT [IsThruComponent vs IsSMTComponent] p7: gap=40 collisioncheckmode=3 verticalgap=30 showdistances=FALSE
ComponentClearance ComponentClearance_THtoTH [IsThruComponent vs IsThruComponent] p8: gap=20 collisioncheckmode=3 verticalgap=20 showdistances=FALSE
ComponentClearance [All] p9: gap=10 collisioncheckmode=3 verticalgap=10 showdistances=FALSE
DiffPairsRouting [All] p1: maxlimit=100 minlimit=10 mostfreqgap=10 toplayer_minwidth=15 toplayer_maxwidth=15 toplayer_prefwidth=15 midlayer1_minwidth=15 midlayer1_maxwidth=15 midlayer1_prefwidth=15 midlayer2_minwidth=15 midlayer2_maxwidth=15 midlayer2_prefwidth=15 midlayer3_minwidth=15 midlayer3_maxwidth=15 midlayer3_prefwidth=15 midlayer4_minwidth=15 midlayer4_maxwidth=15 midlayer4_prefwidth=15 bottomlayer_minwidth=15 bottomlayer_maxwidth=15 bottomlayer_prefwidth=15 maxuncoupledlength=1000
FabricationTestPointUsage TestPointUsage [All] p1: valid=2 allowmultiple=FALSE
FabricationTestpoint Testpoint [All] p1: side=3 testpointundercomponent=TRUE minsize=40 maxsize=100 preferedsize=60 minholesize=0 maxholesize=40 preferedholesize=32 testpointgrid=1 allowsidetop=TRUE allowsidebottom=TRUE usegrid=TRUE gridtolerance=0.01
FanoutControl Fanout_LCC [IsLCC] p1: bgadir=Out bgaviamode=Centered fanoutstyle=Auto fanoutdirection=Alternating viagrid=1 // Fanout_LCC (Default Rule)
FanoutControl Fanout_BGA [IsBGA] p2: bgadir=Out bgaviamode=Centered fanoutstyle=Auto fanoutdirection=Alternating viagrid=1 // Fanout_BGA (Default Rule)
FanoutControl Fanout_Default [All] p4: bgadir=Out bgaviamode=Centered fanoutstyle=Auto fanoutdirection=Alternating viagrid=1 // Fanout_Default (Default Rule)
FanoutControl Fanout_Small [(CompPinCount < 5)] p5: bgadir=Out bgaviamode=Centered fanoutstyle=Auto fanoutdirection=OutThenIn viagrid=1 // Fanout_Small (Default Rule)
HoleSize [All] p1: absolutevalues=TRUE maxlimit=251 minlimit=7.87 maxpercent=80.000 minpercent=20.000
MinimumAnnularRing MinimumAnnularRing_ThermalPadVias [IsVia and InAnyComponent] p1: minimumring=5
MinimumAnnularRing [All] p2: minimumring=5
MinimumSolderMaskSliver MinimumSolderMaskSliver_Logo [InComponentClass('Logo') vs InComponentClass('Logo')] p1: minsoldermaskwidth=0.7
MinimumSolderMaskSliver [All] p2: minsoldermaskwidth=1
PlaneConnect [All] p1: planeconnectstyle=Relief reliefexpansion=10 reliefentries=4 reliefconductorwidth=10 reliefairgap=10
PolygonConnect PolygonConnect_27 [All vs IsNamedPolygon('VBAT1') Or  IsNamedPolygon('CSA') Or  IsNamedPolygon('VBAT1') Or  IsNamedPolygon('CSA') Or  IsNamedPolygon('48Vout1') Or  IsNamedPolygon('CSA') Or  IsNamedPolygon('48Vout1') Or  IsNamedPolygon('SGND') Or  IsNamedPolygon('SGND') Or  IsNamedPolygon('SW2') Or  IsNamedPolygon('CSA') Or  IsNamedPolygon('CSB') Or  IsNamedPolygon('SGND') Or  IsNamedPolygon('CSA') Or  IsNamedPolygon('SW2') Or  IsNamedPolygon('VBAT1') Or  IsNamedPolygon('5V') Or  IsNamedPolygon('48Vout1') Or  IsNamedPolygon('SW2') Or  IsNamedPolygon('VBAT-') Or  IsNamedPolygon('SW2') Or  IsNamedPolygon('SW2') Or  IsNamedPolygon('VBAT1') Or  IsNamedPolygon('VBAT-') Or  IsNamedPolygon('5V') Or  IsNamedPolygon('SW2') Or  IsNamedPolygon('SGND') Or  IsNamedPolygon('SGND') Or  IsNamedPolygon('VBAT-') Or  IsNamedPolygon('VBAT-') Or  IsNamedPolygon('SGND') Or  IsNamedPolygon('SGND') Or  IsNamedPolygon('VBAT-') Or  IsNamedPolygon('CSA') Or  IsNamedPolygon('SGND') Or  IsNamedPolygon('CSA') Or  IsNamedPolygon('SGND') Or  IsNamedPolygon('VDD_2H_D') Or  IsNamedPolygon('VDD_1H_D') Or  IsNamedPolygon('SGND') Or  IsNamedPolygon('CSA') Or  IsNamedPolygon('SW2') Or  IsNamedPolygon('SW2') Or  IsNamedPolygon('SGND') Or  IsNamedPolygon('SGND') Or  IsNamedPolygon('CSA') Or  IsNamedPolygon('SGND') Or  IsNamedPolygon('VBAT1') Or  IsNamedPolygon('SW2')] p1: connectstyle=Direct reliefconductorwidth=10 reliefentries=4 polygonreliefangle="90 Angle" airgapwidth=10
PolygonConnect PolygonConnect_26 [All vs IsNamedPolygon('CSA') Or  IsNamedPolygon('VBAT-') Or  IsNamedPolygon('5V') Or  IsNamedPolygon('SGND') Or  IsNamedPolygon('CSA') Or  IsNamedPolygon('SGND') Or  IsNamedPolygon('VBAT-') Or  IsNamedPolygon('CSA') Or  IsNamedPolygon('SGND') Or  IsNamedPolygon('VBAT1') Or  IsNamedPolygon('SGND') Or  IsNamedPolygon('VBAT1') Or  IsNamedPolygon('SGND') Or  IsNamedPolygon('CSA') Or  IsNamedPolygon('SGND') Or  IsNamedPolygon('CSA') Or  IsNamedPolygon('SGND') Or  IsNamedPolygon('VDD_1H_D') Or  IsNamedPolygon('VBAT-') Or  IsNamedPolygon('CSA') Or  IsNamedPolygon('5V') Or  IsNamedPolygon('SGND') Or  IsNamedPolygon('VBAT-') Or  IsNamedPolygon('CSB') Or  IsNamedPolygon('VBAT1') Or  IsNamedPolygon('CSA') Or  IsNamedPolygon('CSA') Or  IsNamedPolygon('SGND') Or  IsNamedPolygon('SGND') Or  IsNamedPolygon('SGND') Or  IsNamedPolygon('VBAT1') Or  IsNamedPolygon('VBAT-') Or  IsNamedPolygon('CSA') Or  IsNamedPolygon('VDD_2H_D') Or  IsNamedPolygon('VBAT1') Or  IsNamedPolygon('SGND') Or  IsNamedPolygon('CSA') Or  IsNamedPolygon('48Vout1') Or  IsNamedPolygon('SGND') Or  IsNamedPolygon('CSA') Or  IsNamedPolygon('48Vout1') Or  IsNamedPolygon('48Vout1') Or  IsNamedPolygon('CSA')] p2: connectstyle=Direct reliefconductorwidth=10 reliefentries=4 polygonreliefangle="90 Angle" airgapwidth=10
PolygonConnect PolygonConnect_25 [All vs IsNamedPolygon('SGND') Or  IsNamedPolygon('VBAT-') Or  IsNamedPolygon('CSA') Or  IsNamedPolygon('VBAT-') Or  IsNamedPolygon('SGND') Or  IsNamedPolygon('VBAT1') Or  IsNamedPolygon('5V') Or  IsNamedPolygon('CSA') Or  IsNamedPolygon('SGND') Or  IsNamedPolygon('VBAT1') Or  IsNamedPolygon('CSA') Or  IsNamedPolygon('CSA') Or  IsNamedPolygon('CSA') Or  IsNamedPolygon('CSA') Or  IsNamedPolygon('48Vout1') Or  IsNamedPolygon('SGND') Or  IsNamedPolygon('SGND') Or  IsNamedPolygon('48Vout1') Or  IsNamedPolygon('CSA') Or  IsNamedPolygon('VBAT1') Or  IsNamedPolygon('CSA') Or  IsNamedPolygon('SGND') Or  IsNamedPolygon('VBAT1') Or  IsNamedPolygon('5V') Or  IsNamedPolygon('CSB') Or  IsNamedPolygon('CSA') Or  IsNamedPolygon('48Vout1') Or  IsNamedPolygon('CSA') Or  IsNamedPolygon('VBAT1') Or  IsNamedPolygon('VBAT-') Or  IsNamedPolygon('SGND') Or  IsNamedPolygon('SGND') Or  IsNamedPolygon('SGND') Or  IsNamedPolygon('CSA') Or  IsNamedPolygon('SGND') Or  IsNamedPolygon('CSA') Or  IsNamedPolygon('SGND') Or  IsNamedPolygon('SGND') Or  IsNamedPolygon('VBAT-') Or  IsNamedPolygon('VBAT-') Or  IsNamedPolygon('SGND')] p3: connectstyle=Direct reliefconductorwidth=10 reliefentries=4 polygonreliefangle="90 Angle" airgapwidth=10
PolygonConnect PolygonConnect_24 [All vs IsNamedPolygon('SGND') Or  IsNamedPolygon('VBAT1') Or  IsNamedPolygon('SGND') Or  IsNamedPolygon('SGND') Or  IsNamedPolygon('SGND') Or  IsNamedPolygon('CSA') Or  IsNamedPolygon('VBAT1') Or  IsNamedPolygon('CSA') Or  IsNamedPolygon('48Vout1') Or  IsNamedPolygon('VBAT-') Or  IsNamedPolygon('SGND') Or  IsNamedPolygon('SGND') Or  IsNamedPolygon('SGND') Or  IsNamedPolygon('CSA') Or  IsNamedPolygon('5V') Or  IsNamedPolygon('SGND') Or  IsNamedPolygon('48Vout1') Or  IsNamedPolygon('VBAT1') Or  IsNamedPolygon('CSA') Or  IsNamedPolygon('SGND') Or  IsNamedPolygon('CSA') Or  IsNamedPolygon('CSA') Or  IsNamedPolygon('SGND') Or  IsNamedPolygon('CSB') Or  IsNamedPolygon('VBAT1') Or  IsNamedPolygon('CSA') Or  IsNamedPolygon('SGND') Or  IsNamedPolygon('CSA') Or  IsNamedPolygon('CSA') Or  IsNamedPolygon('CSA') Or  IsNamedPolygon('SGND') Or  IsNamedPolygon('SGND') Or  IsNamedPolygon('48Vout1')] p4: connectstyle=Direct reliefconductorwidth=10 reliefentries=4 polygonreliefangle="90 Angle" airgapwidth=10
PolygonConnect PolygonConnect_23 [All vs IsNamedPolygon('CSB') Or  IsNamedPolygon('48Vout1') Or  IsNamedPolygon('CSA') Or  IsNamedPolygon('CSA') Or  IsNamedPolygon('VBAT1') Or  IsNamedPolygon('VBAT1')] p5: connectstyle=Direct reliefconductorwidth=10 reliefentries=4 polygonreliefangle="90 Angle" airgapwidth=10
PolygonConnect PolygonConnect_22 [All vs IsNamedPolygon('CSA') Or  IsNamedPolygon('VBAT1') Or  IsNamedPolygon('CSA') Or  IsNamedPolygon('VBAT1') Or  IsNamedPolygon('CSB')] p6: connectstyle=Direct reliefconductorwidth=10 reliefentries=4 polygonreliefangle="90 Angle" airgapwidth=10
PolygonConnect PolygonConnect_21 [All vs IsNamedPolygon('VBAT1') Or  IsNamedPolygon('VBAT1') Or  IsNamedPolygon('CSA')] p7: connectstyle=Direct reliefconductorwidth=10 reliefentries=4 polygonreliefangle="90 Angle" airgapwidth=10
PolygonConnect PolygonConnect_20 [All vs IsNamedPolygon('VBAT1')] p8: connectstyle=Direct reliefconductorwidth=10 reliefentries=4 polygonreliefangle="90 Angle" airgapwidth=10
PolygonConnect PolygonConnect_19 [All vs IsNamedPolygon('SGND') Or  IsNamedPolygon('SGND') Or  IsNamedPolygon('SGND') Or  IsNamedPolygon('CSA') Or  IsNamedPolygon('VBAT_DISCH_IN') Or  IsNamedPolygon('VBAT_DISCH_IN') Or  IsNamedPolygon('VBAT_DISCH_IN') Or  IsNamedPolygon('CSB_DISCH') Or  IsNamedPolygon('SGND') Or  IsNamedPolygon('5V') Or  IsNamedPolygon('SGND') Or  IsNamedPolygon('SNGD') Or  IsNamedPolygon('SGND') Or  IsNamedPolygon('SGND') Or  IsNamedPolygon('CSA') Or  IsNamedPolygon('SGND') Or  IsNamedPolygon('SGND') Or  IsNamedPolygon('CSA_DISCH') Or  IsNamedPolygon('48V_DISCH_OUT') Or  IsNamedPolygon('VBAT_DISCH_IN') Or  IsNamedPolygon('SGND') Or  IsNamedPolygon('SGND') Or  IsNamedPolygon('48V_DISCH_OUT') Or  IsNamedPolygon('SGND') Or  IsNamedPolygon('CSA_DISCH') Or  IsNamedPolygon('5V') Or  IsNamedPolygon('SGND') Or  IsNamedPolygon('SGND') Or  IsNamedPolygon('48V_DISCH_OUT') Or  IsNamedPolygon('48V_DISCH_OUT') Or  IsNamedPolygon('SGND') Or  IsNamedPolygon('12V_AUX') Or  IsNamedPolygon('48V_DISCH_OUT') Or  IsNamedPolygon('VBAT_DISCH_IN') Or  IsNamedPolygon('VBAT_DISCH_IN') Or  IsNamedPolygon('SGND')] p9: connectstyle=Direct reliefconductorwidth=10 reliefentries=4 polygonreliefangle="90 Angle" airgapwidth=10
PolygonConnect PolygonConnect_18 [All vs IsNamedPolygon('CSA') Or  IsNamedPolygon('VBAT_DISCH_IN') Or  IsNamedPolygon('VBAT_DISCH_IN') Or  IsNamedPolygon('VBAT_DISCH_IN') Or  IsNamedPolygon('48V_DISCH_OUT') Or  IsNamedPolygon('VBAT_DISCH_IN') Or  IsNamedPolygon('SGND') Or  IsNamedPolygon('SGND') Or  IsNamedPolygon('SGND') Or  IsNamedPolygon('SGND') Or  IsNamedPolygon('SGND') Or  IsNamedPolygon('VBAT_DISCH_IN') Or  IsNamedPolygon('SGND') Or  IsNamedPolygon('CSA_DISCH') Or  IsNamedPolygon('SGND') Or  IsNamedPolygon('48V_DISCH_OUT') Or  IsNamedPolygon('48V_DISCH_OUT') Or  IsNamedPolygon('5V') Or  IsNamedPolygon('SGND') Or  IsNamedPolygon('SGND') Or  IsNamedPolygon('SGND') Or  IsNamedPolygon('SGND') Or  IsNamedPolygon('12V_AUX') Or  IsNamedPolygon('CSA_DISCH') Or  IsNamedPolygon('CSB_DISCH') Or  IsNamedPolygon('SGND') Or  IsNamedPolygon('SGND') Or  IsNamedPolygon('VBAT_DISCH_IN')] p10: connectstyle=Direct reliefconductorwidth=10 reliefentries=4 polygonreliefangle="90 Angle" airgapwidth=10
PolygonConnect PolygonConnect_17 [All vs IsNamedPolygon('SGND') Or  IsNamedPolygon('VBAT_DISCH_IN') Or  IsNamedPolygon('SGND') Or  IsNamedPolygon('VBAT_DISCH_IN') Or  IsNamedPolygon('CSA_DISCH') Or  IsNamedPolygon('VBAT_DISCH_IN') Or  IsNamedPolygon('VBAT_DISCH_IN') Or  IsNamedPolygon('SGND') Or  IsNamedPolygon('SGND') Or  IsNamedPolygon('48V_DISCH_OUT') Or  IsNamedPolygon('CSA_DISCH') Or  IsNamedPolygon('SGND') Or  IsNamedPolygon('VBAT_DISCH_IN') Or  IsNamedPolygon('SGND') Or  IsNamedPolygon('5V') Or  IsNamedPolygon('48V_DISCH_OUT') Or  IsNamedPolygon('SGND') Or  IsNamedPolygon('CSB_DISCH') Or  IsNamedPolygon('CSA') Or  IsNamedPolygon('SGND') Or  IsNamedPolygon('48V_DISCH_OUT') Or  IsNamedPolygon('SGND') Or  IsNamedPolygon('VBAT_DISCH_IN')] p11: connectstyle=Direct reliefconductorwidth=10 reliefentries=4 polygonreliefangle="90 Angle" airgapwidth=10
PolygonConnect PolygonConnect_16 [All vs IsNamedPolygon('SGND') Or  IsNamedPolygon('SGND') Or  IsNamedPolygon('CSA_DISCH') Or  IsNamedPolygon('48V_DISCH_OUT') Or  IsNamedPolygon('VBAT_DISCH_IN') Or  IsNamedPolygon('SGND') Or  IsNamedPolygon('SGND') Or  IsNamedPolygon('SGND') Or  IsNamedPolygon('SGND') Or  IsNamedPolygon('VBAT_DISCH_IN') Or  IsNamedPolygon('VBAT_DISCH_IN') Or  IsNamedPolygon('CSB_DISCH') Or  IsNamedPolygon('SGND') Or  IsNamedPolygon('VBAT_DISCH_IN') Or  IsNamedPolygon('VBAT_DISCH_IN') Or  IsNamedPolygon('SGND') Or  IsNamedPolygon('VBAT_DISCH_IN') Or  IsNamedPolygon('CSA') Or  IsNamedPolygon('CSA_DISCH') Or  IsNamedPolygon('SGND')] p12: connectstyle=Direct reliefconductorwidth=10 reliefentries=4 polygonreliefangle="90 Angle" airgapwidth=10
PolygonConnect PolygonConnect_15 [All vs IsNamedPolygon('CSA_DISCH') Or  IsNamedPolygon('SGND') Or  IsNamedPolygon('SGND') Or  IsNamedPolygon('48V_DISCH_OUT') Or  IsNamedPolygon('VBAT_DISCH_IN') Or  IsNamedPolygon('CSA') Or  IsNamedPolygon('VBAT_DISCH_IN') Or  IsNamedPolygon('SGND') Or  IsNamedPolygon('VBAT_DISCH_IN') Or  IsNamedPolygon('CSB_DISCH') Or  IsNamedPolygon('VBAT_DISCH_IN') Or  IsNamedPolygon('CSA_DISCH') Or  IsNamedPolygon('VBAT_DISCH_IN')] p13: connectstyle=Direct reliefconductorwidth=10 reliefentries=4 polygonreliefangle="90 Angle" airgapwidth=10
PolygonConnect PolygonConnect_14 [All vs IsNamedPolygon('CSA') Or  IsNamedPolygon('48V_DISCH_OUT') Or  IsNamedPolygon('SGND') Or  IsNamedPolygon('SGND') Or  IsNamedPolygon('CSA_DISCH') Or  IsNamedPolygon('CSB_DISCH')] p14: connectstyle=Direct reliefconductorwidth=10 reliefentries=4 polygonreliefangle="90 Angle" airgapwidth=10
PolygonConnect PolygonConnect_13 [All vs IsNamedPolygon('SGND') Or  IsNamedPolygon('48V_DISCH_OUT') Or  IsNamedPolygon('SGND') Or  IsNamedPolygon('CSB_DISCH') Or  IsNamedPolygon('CSA_DISCH')] p15: connectstyle=Direct reliefconductorwidth=10 reliefentries=4 polygonreliefangle="90 Angle" airgapwidth=10
PolygonConnect PolygonConnect_12 [All vs IsNamedPolygon('48V_DISCH_OUT') Or  IsNamedPolygon('SGND') Or  IsNamedPolygon('SGND')] p16: connectstyle=Direct reliefconductorwidth=10 reliefentries=4 polygonreliefangle="90 Angle" airgapwidth=10
PolygonConnect PolygonConnect_11 [All vs IsNamedPolygon('GND') Or  IsNamedPolygon('D101_2') Or  IsNamedPolygon('V+') Or  IsNamedPolygon('GND') Or  IsNamedPolygon('C128_1') Or  IsNamedPolygon('J2_2') Or  IsNamedPolygon('CS') Or  IsNamedPolygon('V+') Or  IsNamedPolygon('GND') Or  IsNamedPolygon('J2_2') Or  IsNamedPolygon('PGND') Or  IsNamedPolygon('12V') Or  IsNamedPolygon('PGND') Or  IsNamedPolygon('PGND') Or  IsNamedPolygon('V+') Or  IsNamedPolygon('V+') Or  IsNamedPolygon('D101_2') Or  IsNamedPolygon('CS') Or  IsNamedPolygon('GND')] p17: connectstyle=Direct reliefconductorwidth=10 reliefentries=4 polygonreliefangle="90 Angle" airgapwidth=10
PolygonConnect PolygonConnect_10 [All vs IsNamedPolygon('GND') Or  IsNamedPolygon('C128_1') Or  IsNamedPolygon('GND') Or  IsNamedPolygon('J2_2') Or  IsNamedPolygon('GND') Or  IsNamedPolygon('D101_2') Or  IsNamedPolygon('J2_2') Or  IsNamedPolygon('V+') Or  IsNamedPolygon('PGND') Or  IsNamedPolygon('CS') Or  IsNamedPolygon('V+')] p18: connectstyle=Direct reliefconductorwidth=10 reliefentries=4 polygonreliefangle="90 Angle" airgapwidth=10
PolygonConnect PolygonConnect_9 [All vs IsNamedPolygon('J2_2') Or  IsNamedPolygon('GND') Or  IsNamedPolygon('8V5') Or  IsNamedPolygon('V+') Or  IsNamedPolygon('R117_1') Or  IsNamedPolygon('PGND') Or  IsNamedPolygon('PGND') Or  IsNamedPolygon('Drv') Or  IsNamedPolygon('V+') Or  IsNamedPolygon('V+') Or  IsNamedPolygon('C128_1') Or  IsNamedPolygon('GND') Or  IsNamedPolygon('GND') Or  IsNamedPolygon('J2_2') Or  IsNamedPolygon('PGND')] p19: connectstyle=Direct reliefconductorwidth=10 reliefentries=4 polygonreliefangle="90 Angle" airgapwidth=10
PolygonConnect PolygonConnect_8 [All vs IsNamedPolygon('8V5') Or  IsNamedPolygon('J2_2') Or  IsNamedPolygon('PGND') Or  IsNamedPolygon('GND') Or  IsNamedPolygon('GND') Or  IsNamedPolygon('V+') Or  IsNamedPolygon('J2_2') Or  IsNamedPolygon('V+') Or  IsNamedPolygon('C128_1') Or  IsNamedPolygon('V+') Or  IsNamedPolygon('PGND') Or  IsNamedPolygon('J2_2') Or  IsNamedPolygon('J2_2') Or  IsNamedPolygon('R117_1')] p20: connectstyle=Direct reliefconductorwidth=10 reliefentries=4 polygonreliefangle="90 Angle" airgapwidth=10
PolygonConnect PolygonConnect_7 [All vs IsNamedPolygon('J2_2') Or  IsNamedPolygon('J2_2') Or  IsNamedPolygon('J2_2') Or  IsNamedPolygon('C128_1') Or  IsNamedPolygon('J2_2')] p21: connectstyle=Direct reliefconductorwidth=10 reliefentries=4 polygonreliefangle="90 Angle" airgapwidth=10
PolygonConnect PolygonConnect_6 [All vs IsNamedPolygon('J2_2')] p22: connectstyle=Direct reliefconductorwidth=10 reliefentries=4 polygonreliefangle="90 Angle" airgapwidth=10
PolygonConnect PolygonConnect_5 [All vs IsNamedPolygon('GND') Or  IsNamedPolygon('Vout') Or  IsNamedPolygon('Bottom Layer-SW') Or  IsNamedPolygon('GND') Or  IsNamedPolygon('C1_1') Or  IsNamedPolygon('Q1_3') Or  IsNamedPolygon('J2_2') Or  IsNamedPolygon('GND') Or  IsNamedPolygon('J2_2') Or  IsNamedPolygon('GND') Or  IsNamedPolygon('Vout') Or  IsNamedPolygon('Top Layer-SW') Or  IsNamedPolygon('Q1_3') Or  IsNamedPolygon('GND') Or  IsNamedPolygon('J2_2') Or  IsNamedPolygon('J2_2') Or  IsNamedPolygon('GND') Or  IsNamedPolygon('GND') Or  IsNamedPolygon('GND') Or  IsNamedPolygon('GND') Or  IsNamedPolygon('GND')] p23: connectstyle=Direct reliefconductorwidth=10 reliefentries=4 polygonreliefangle="90 Angle" airgapwidth=10
PolygonConnect PolygonConnect_4 [All vs IsNamedPolygon('GND') Or  IsNamedPolygon('Bottom Layer-SW') Or  IsNamedPolygon('C1_1') Or  IsNamedPolygon('Top Layer-SW') Or  IsNamedPolygon('GND') Or  IsNamedPolygon('GND') Or  IsNamedPolygon('GND') Or  IsNamedPolygon('Q1_3') Or  IsNamedPolygon('Vout') Or  IsNamedPolygon('Q1_3') Or  IsNamedPolygon('Vout')] p24: connectstyle=Direct reliefconductorwidth=10 reliefentries=4 polygonreliefangle="90 Angle" airgapwidth=10
PolygonConnect PolygonConnect_3 [All vs IsNamedPolygon('Q1_3') Or  IsNamedPolygon('Q1_3') Or  IsNamedPolygon('Top Layer-SW') Or  IsNamedPolygon('C1_1') Or  IsNamedPolygon('Bottom Layer-SW')] p25: connectstyle=Direct reliefconductorwidth=10 reliefentries=4 polygonreliefangle="90 Angle" airgapwidth=10
PolygonConnect PolygonConnect_2 [All vs IsNamedPolygon('Top Layer-SW') Or  IsNamedPolygon('Bottom Layer-SW')] p26: connectstyle=Direct reliefconductorwidth=10 reliefentries=4 polygonreliefangle="90 Angle" airgapwidth=10
PolygonConnect PolygonConnect_1 [All vs IsNamedPolygon('Bottom Layer-SW') Or  IsNamedPolygon('Top Layer-SW')] p27: thpad.connectstyle=Direct thpad.reliefconductorwidth=10 thpad.reliefentries=4 thpad.polygonreliefangle="90 Angle" thpad.airgapwidth=10 smdpad.connectstyle=Direct smdpad.reliefconductorwidth=10 smdpad.reliefentries=4 smdpad.polygonreliefangle="90 Angle" smdpad.airgapwidth=10 via.connectstyle=Relief via.reliefconductorwidth=10 via.reliefentries=4 via.polygonreliefangle="90 Angle" via.airgapwidth=10
PolygonConnect [All] p28: connectstyle=Relief reliefconductorwidth=10 reliefentries=4 polygonreliefangle="90 Angle" airgapwidth=10
RoutingVias ThermalPadVias [IsVia and InAnyComponent] p1: holewidth=7.87 width=19.68 viastyle="Through Hole" minholewidth=7.87 minwidth=19.68 maxholewidth=12.99 maxwidth=23.62
RoutingVias [All] p2: holewidth=10 width=20 viastyle="Through Hole" minholewidth=7.87 minwidth=20 maxholewidth=40 maxwidth=65
SilkToBoardRegionClearance [Not ((IsComment or IsDesignator) And (Hide <> 'False')) and not InRegion(1000,500,4000,800)] p1:
SilkToSilkClearance SilkToSilkClearance_Pb-FreeLogo [(HasFootprint('Pb-Free_Overlay_Medium') OR HasFootprint('Pb-Free_Overlay_Small')) vs (HasFootprint('Pb-Free_Overlay_Medium') OR HasFootprint('Pb-Free_Overlay_Small'))] p1: silktosilkclearance=0
SilkToSilkClearance [All] p2: silktosilkclearance=4
SilkToSolderMaskClearance SilkToComponentPadClearance [(IsPad or IsFill or IsRegion) and InAnycomponent] p1: minsilkscreentomaskgap=5 clearancetoexposedcopper=TRUE
SilkToSolderMaskClearance "Silk to Solder Mask Opening" [All] p2: minsilkscreentomaskgap=0.5 clearancetoexposedcopper=FALSE
SolderMaskExpansion [All] p1: expansion=1.97
Width [All] p1: maxlimit=100 minlimit=6 preferedwidth=10 checkconnectedcopper=TRUE
15 further rules are at their usual default settings.

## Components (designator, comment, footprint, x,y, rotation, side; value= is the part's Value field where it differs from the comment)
C100 "GRJ31CC72A475KE01L" 1206_180 866.14,70.84 r0 bottom value=4.7uF
C101 "GRJ31CC72A475KE01L" 1206_180 867.01,342.17 r0 bottom value=4.7uF
C102 "GRJ31CC72A475KE01L" 1206_180 867.01,437.61 r0 bottom value=4.7uF
C103 "GRJ31CC72A475KE01L" 1206_180 1144.05,417.07 r0 top value=4.7uF
C104 "GRJ31CC72A475KE01L" 1206_180 865.71,161.28 r0 bottom value=4.7uF
C105 "GRJ31CC72A475KE01L" 1206_180 1144.47,1552.39 r0 top value=4.7uF
C106 "MBASH168SC7224KTCA01" 0603 871.79,566.93 r270 bottom value=0.22uF
C107 "MBASH168SC7224KTCA01" 0603 943.27,566.93 r270 bottom value=0.22uF
C108 "MBASH168SC7224KTCA01" 0603 1014.74,566.93 r270 bottom value=0.22uF
C109 "MBASH168SC7224KTCA01" 0603 1086.22,566.93 r270 bottom value=0.22uF
C110 "MBASH168SC7224KTCA01" 0603 1166.09,1845.24 r0 top value=0.22uF
C111 "MBASH168SC7224KTCA01" 0603 1166.09,1773.76 r0 top value=0.22uF
C112 "MBASH168SC7224KTCA01" 0603 1166.09,1702.29 r0 top value=0.22uF
C113 "MBASH168SC7224KTCA01" 0603 1166.09,1630.81 r0 top value=0.22uF
C114 "MBASH168SC7224KTCA01" 0603 1815,710.13 r0 bottom value=0.22uF
C115 "MBASH168SC7224KTCA01" 0603 1819.42,1510.75 r0 top value=0.22uF
C116 "MBASH168SC7224KTCA01" 0603 1815,638.66 r0 bottom value=0.22uF
C117 "MBASH168SC7224KTCA01" 0603 1819.42,1579.15 r0 top value=0.22uF
C118 "MBASH168SC7224KTCA01" 0603 1819.42,1865.06 r0 top value=0.22uF
C119 "MBASH168SC7224KTCA01" 0603 1819.42,1793.58 r0 top value=0.22uF
C120 "MBASH168SC7224KTCA01" 0603 1819.42,1722.11 r0 top value=0.22uF
C121 "MBASH168SC7224KTCA01" 0603 1819.42,1650.63 r0 top value=0.22uF
C122 "GRJ31CC72A475KE01L" 1206_180 1780,560.16 r0 bottom value=4.7uF
C123 "GRJ31CC72A475KE01L" 1206_180 1781.89,1432.32 r0 top value=4.7uF
C124 "GRJ31CC72A475KE01L" 1206_180 1781.89,1336.88 r0 top value=4.7uF
C125 "GRJ31CC72A475KE01L" 1206_180 1781.89,1246.44 r0 top value=4.7uF
C126 "GRJ31CC72A475KE01L" 1206_180 1781.89,1151 r0 top value=4.7uF
C127 "GRJ31CC72A475KE01L" 1206_180 1781.89,1055.55 r0 top value=4.7uF
C128 "GRJ31CC72A475KE01L" 1206_180 1781.89,960.11 r0 top value=4.7uF
C129 "0402YC104KAT2A" 0402 1007.54,2176.32 r90 bottom value=0.1uF
C130 "0402YC104KAT2A" 0402 1641.28,2121.12 r0 bottom value=0.1uF
C131 "GRM1555C1H100JA01D" 0402 1158.04,2055.79 r90 bottom value=10pF
C132 "GRM1555C1H100JA01D" 0402 871.65,1942.21 r270 bottom value=10pF
C133 "GRM1555C1H100JA01D" 0402 1526.98,1942.63 r270 bottom value=10pF
C134 "GRM1555C1H100JA01D" 0402 1813.36,2056.11 r90 bottom value=10pF
C135 "GRM033R61E104KE14J" 0201_033 1120.32,1935.76 r270 top value=0.1uF
C136 "GRM033R61E104KE14J" 0201_033 1773.66,1940 r270 top value=0.1uF
C137 "0402YC104KAT2A" 0402 535.09,2001.92 r270 bottom value=0.1uF
C138 "0402YC104KAT2A" 0402 1252.44,2152.61 r90 bottom value=0.1uF
C139 "GRM1555C1H100JA01D" 0402 649.62,1942.15 r270 bottom value=10pF
C140 "GRM1555C1H100JA01D" 0402 710.04,1942.66 r270 bottom value=10pF
C141 "GRM1555C1H100JA01D" 0402 1367.9,1941.85 r270 bottom value=10pF
C142 "GRM1555C1H100JA01D" 0402 1305.58,1941.61 r270 bottom value=10pF
C143 "GRM033R61E104KE14J" 0201_033 849.32,1921.93 r270 top value=0.1uF
C144 "GRM033R61E104KE14J" 0201_033 1502.65,1919.47 r270 top value=0.1uF
C145 "63PFV22M6.3X8" SM_RADIAL_D 1772.17,370.08 r0 bottom value=22uF
C146 "63PFV22M6.3X8" SM_RADIAL_D 1435.39,263.78 r180 bottom value=22uF
C147 "63PFV22M6.3X8" SM_RADIAL_D 1435.39,548.51 r180 bottom value=22uF
C148 "GRJ31CC72A475KE01L" 1206_180 1144.47,1456.94 r0 top value=4.7uF
C149 "GRJ31CC72A475KE01L" 1206_180 1144.47,1361.5 r0 top value=4.7uF
C150 "GRJ31CC72A475KE01L" 1206_180 1144.47,1266.06 r0 top value=4.7uF
C151 "GRJ31CC72A475KE01L" 1206_180 1144.47,1170.61 r0 top value=4.7uF
C152 "GRJ31CC72A475KE01L" 1206_180 1144.47,1075.17 r0 top value=4.7uF
C153 "GRJ31CC72A475KE01L" 1206_180 1144.47,979.73 r0 top value=4.7uF
C154 "GRJ31CC72A475KE01L" 1206_180 1142.23,884.28 r0 top value=4.7uF
C155 "GRJ31CC72A475KE01L" 1206_180 1142.23,788.84 r0 top value=4.7uF
C156 "GRJ31CC72A475KE01L" 1206_180 1142.23,693.4 r0 top value=4.7uF
C157 "GRJ31CC72A475KE01L" 1206_180 1144.3,602.96 r0 top value=4.7uF
C158 "GRJ31CC72A475KE01L" 1206_180 1144.3,507.51 r0 top value=4.7uF
C159 "GRJ31CC72A475KE01L" 1206_180 867.26,251.73 r0 bottom value=4.7uF
C160 "GRJ31CC72A475KE01L" 1206_180 1781.89,864.67 r0 top value=4.7uF
C161 "GRJ31CC72A475KE01L" 1206_180 1781.89,769.22 r0 top value=4.7uF
C162 "GRJ31CC72A475KE01L" 1206_180 1781.89,673.78 r0 top value=4.7uF
C163 "GRJ31CC72A475KE01L" 1206_180 1781.89,578.24 r0 top value=4.7uF
C164 "GRJ31CC72A475KE01L" 1206_180 1781.89,482.8 r0 top value=4.7uF
C165 "GRJ31CC72A475KE01L" 1206_180 1779.53,392.35 r0 top value=4.7uF
C166 "GRM155R70J104KA01D" 0402 255,1433.62 r270 bottom value=0.1uF
C167 "GRM155R70J104KA01D" 0402 180,1318.62 r180 bottom value=0.1uF
C168 "04025U100CAT2A" 0402 345,1635 r0 top value=10pF
C169 "GRM21BC71C106KE11L" 0805_HV 270,620 r0 top value=10uF
C170 "GCM155R71E153KA55D" 0402 120,970 r180 top value=0.015uF
C171 "GCM155R71E153KA55D" 0402 262.45,690 r0 top value=0.015uF
C172 "0402ZC103KAT2A" 0402 1611.8,2180 r90 bottom value=0.01uF
C173 "GCM155R71E153KA55D" 0402 307.35,970 r180 top value=0.015uF
C174 "GRM21BZ71A226ME15L" 0805_HV 102.35,1040 r180 top value=22uF
C175 "CGA2B3X7R1E104K050BB" 0402 199.43,1465.1 r270 top value=0.1uF
C176 "04025U100CAT2A" 0402 393.87,1547.84 r0 top value=10pF
C177 "GRM21BC71C106KE11L" 0805_HV 76.13,620 r0 top value=10uF
C179 "GCM155R71E153KA55D" 0402 68.73,690 r0 top value=0.015uF
C180 "GRM188R72A182KA01D" 0603 853.59,1815.06 r90 bottom value=1800pF
C181 "GRM188R72A182KA01D" 0603 1503.2,1818.24 r90 bottom value=1800pF
C182 "0402YC104KAT2A" 0402 1080.72,2061.43 r270 top value=0.1uF
C183 "0402YC104KAT2A" 0402 1736.05,2061.43 r270 top value=0.1uF
C184 "06035A680JAT2A" 0603 516.07,1411.73 r270 top value=68pF
C185 "GRM1555C1H470FA01D" 0402 459.62,1465 r270 top value=47pF
C186 "GRM1555C1H470FA01D" 0402 459.62,1360 r90 top value=47pF
C187 "C1608X7R1C105K080AC" 0603 140,1460 r270 top value=1uF
C188 "GRM155R70J104KA01D" 0402 516.07,1410 r270 bottom value=0.1uF
C189 "0402ZC103KAT2A" 0402 961.8,2176.32 r90 bottom value=0.01uF
C191 "GRM21BZ71A226ME15L" 0805_HV 287.54,1040 r180 top value=22uF
C192 "04025U100CAT2A" 0402 412.65,1475 r270 top value=10pF
D100 "STPS30M100DJF-TR" FP-STPS30M100DJF-TR_PowerFlat6-MFG 1707.16,1771.87 r90 bottom
D101 "STPS30M100DJF-TR" FP-STPS30M100DJF-TR_PowerFlat6-MFG 1044.3,1773.05 r90 bottom
D102 "STPS30M100DJF-TR" FP-STPS30M100DJF-TR_PowerFlat6-MFG 1480.32,1582.68 r270 top
D103 "STPS30M100DJF-TR" FP-STPS30M100DJF-TR_PowerFlat6-MFG 789.11,1595.23 r270 top
J100 "M50-3900642" FP-M50-3900642_HDR12-MFG 196.85,19.68 r0 top
L100 "IHLP8787MZER2R2M5A" IHLP8787MZ 1266.42,1208.92 r0 bottom value=2.2uH
LOGO100 "CAUTION HOT SURFACE" IEC_HotSurface_Small 210.16,2030 r90 top
Logo101 "Pb-Free Symbol" Pb-Free_Overlay_Medium 423.51,2040.58 r90 top
Logo102 "WEEE logo" WEEE_Minimum 216.54,2257.8 r90 top
Logo103 "FCC disclaimer" FCC_disclaimer 2259.84,708.66 r90 top
R100 "CRCW04023R01FKED" 0402 924.66,2050.22 r270 bottom value=3.01
R101 "CRCW04023R01FKED" 0402 1579.99,2050 r270 bottom value=3.01
R102 "KRL2012E-M-R002-G-T5" 0508 741.6,1415.67 r270 top value=0.002
R103 "KRL2012E-M-R002-G-T5" 0508 865.21,1415.67 r270 top value=0.002
R104 "CRCW04020000Z0ED" 0402 1111.11,2136.3 r0 bottom value=0
R105 "CRCW04020000Z0ED" 0402 871.65,2050.22 r270 bottom value=0
R106 "CRCW04020000Z0ED" 0402 1526.98,2050.64 r270 bottom value=0
R107 "CRCW04020000Z0ED" 0402 1764.44,2136.62 r180 bottom value=0
R108 "CRCW04020000Z0ED" 0402 818.64,1996.97 r90 bottom value=0
R109 "CRCW04020000Z0ED" 0402 1473.97,1997.02 r90 bottom value=0
R110 "RC0603FR-07100RL" 0603 578.59,1410 r270 bottom value=100
R111 "CRCW04023R01FKED" 0402 593.91,2050.77 r270 bottom value=3.01
R112 "CRCW04023R01FKED" 0402 1252.44,2049.92 r270 bottom value=3.01
R113 "CRCW04020000Z0ED" 0402 709.52,2050.67 r270 bottom value=0
R114 "CRCW04020000Z0ED" 0402 1367.9,2049.86 r270 bottom value=0
R115 "CRCW12062R55FKEA" 1206 720,1830 r0 bottom value=2.55
R116 "CRCW12062R55FKEA" 1206 1369.5,1833.96 r180 bottom value=2.55
R117 "CRCW04020000Z0ED" 0402 650.77,2050.22 r270 bottom value=0
R118 "CRCW04020000Z0ED" 0402 1305.58,2049.62 r270 bottom value=0
R119 "KRL2012E-M-R002-G-T5" 0508 530,1830 r0 top value=0.002
R120 "RC0603FR-07100RL" 0603 615.33,1447.87 r0 top value=100
R121 "RC0603FR-07100RL" 0603 645,1410 r90 bottom value=100
R122 "RC0603FR-07100RL" 0603 615.33,1381.46 r0 top value=100
R123 "KRL2012E-M-R002-G-T5" 0508 530,1710 r0 top value=0.002
R124 "CRCW04020000Z0ED" 0402 345,1435 r270 bottom value=0
R127 "CRCW040233K2FKED" 0402 345,1590 r0 top value=33.2k
R128 "CRCW04020000Z0ED" 0402 300,1435 r270 bottom value=0
R129 "CRCW040233K2FKED" 0402 365.4,1475 r90 top value=33.2k
R327 "CRCW04021K00FKED" 0402 447.13,1635 r180 top value=1.00k
R328 "CRCW04021K00FKED" 0402 490,1590 r180 top value=1.00k
TP100 "5003" Keystone5003 494.46,289.13 r90 bottom
TP101 "5003" Keystone5003 362.45,287.4 r90 bottom
TP102 "5003" Keystone5003 230.44,287.4 r90 bottom
TP103 "5003" Keystone5003 98.43,287.4 r90 bottom
TP104 "5001" Keystone5001 407.64,23.38 r90 bottom
TP105 "5001" Keystone5001 428.01,155.39 r90 bottom
U100 "ISO6521REU" REU0008A-MFG 1025.6,2058 r180 bottom
U101 "LMG3100R017" VBE0015A-MFG 997.13,1857.21 r0 top
U102 "LMG3100R017" VBE0015A-MFG 1650.46,1857.21 r0 top
U103 "ISO6521REU" REU0008A-MFG 1680.93,2058.32 r180 bottom
U104 "LMG3100R017" VBE0015A-MFG 726.12,1857.21 r0 top
U105 "LMG3100R017" VBE0015A-MFG 1379.45,1856.97 r0 top
U106 "TLV71333PDBVR" DBV0005A_N 155,1432.24 r90 bottom
U107 "UCC33420" RAQ0012B-MFG 96.06,833.62 r90 top
U108 "UCC33420" RAQ0012B-MFG 282.92,835 r90 top
U109 "TLV365DBVRQ1" DBV0005A-MFG 285,1487.76 r90 top
U110 "INA296A3IDDF" DDF0008A-MFG 429.53,1414.83 r90 bottom
VBAT100 "3620-2-32-15-00-00-08-0" Mill-Max_3620-2-32-xx-00-00-08-0 550,-157.48 r0 top
VBAT101 "3620-2-32-15-00-00-08-0" Mill-Max_3620-2-32-xx-00-00-08-0 710,-157.48 r0 top
VBAT-100 "3620-2-32-15-00-00-08-0" Mill-Max_3620-2-32-xx-00-00-08-0 1110,-157.48 r0 top
VBAT-101 "3620-2-32-15-00-00-08-0" Mill-Max_3620-2-32-xx-00-00-08-0 1270,-157.48 r0 top
VBAT-102 "3620-2-32-15-00-00-08-0" Mill-Max_3620-2-32-xx-00-00-08-0 950,-157.48 r0 top
VBAT-103 "3620-2-32-15-00-00-08-0" Mill-Max_3620-2-32-xx-00-00-08-0 1430,-157.48 r0 top
VOUT100 "3620-2-32-15-00-00-08-0" Mill-Max_3620-2-32-xx-00-00-08-0 1830,-157.48 r0 top
VOUT101 "3620-2-32-15-00-00-08-0" Mill-Max_3620-2-32-xx-00-00-08-0 1670,-157.48 r0 top

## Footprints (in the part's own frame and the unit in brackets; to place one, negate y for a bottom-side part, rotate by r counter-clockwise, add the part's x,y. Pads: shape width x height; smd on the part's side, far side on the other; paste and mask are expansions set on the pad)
0201_033 [mm] "SMD, 2-Leads, Height 0.33mm"
  rect 0.46x0.42 smd mask+0.048: 1(-0.33,0) 2(0.33,0)
  body extent -0.31,-0.16 0.31,0.16, height 0.33
0402 [mm] "0402 from SM-752 data"
  rect 0.8x0.6 smd: 1(-0.6,0) 2(0.6,0)
  silkscreen extent -1.22,-0.52 1.22,0.52, body extent -0.55,-0.3 0.55,0.3, height 0.6
0508 [mm] "IPC nominal based on TDK C1220 type capacitors e4162_c.pdf"
  rect 0.8x2.25 smd: 1(-0.75,0) 2(0.75,0)
  silkscreen extent -1.44,-1.42 1.44,1.42, body extent -0.72,-1.1 0.72,1.1, height 1
0603 [mm] "0603 from SM-752 data"
  rect 1x0.95 smd: 1(-0.8,0) 2(0.8,0)
  silkscreen extent -1.52,-0.69 1.52,0.69, body extent -0.87,-0.47 0.87,0.47, height 1
0805_HV [mil] "0805 with 30mil clearance between pads"
  rect 50x63 smd: 1(-40,0) 2(40,0)
  silkscreen extent -74,-40 74,40, body extent -43,-29 43,29, height 57
1206 [mm] "1206 from SM-752 data"
  rect 1.3x1.85 smd: 1(-1.45,0) 2(1.45,0)
  silkscreen extent -2.4,-1.21 2.4,1.21, body extent -1.7,-0.9 1.7,0.9, height 1.35
1206_180 [mm] "1206_180"
  rect 1.1x1.6 smd: 1(-1.7,0) 2(1.7,0)
  silkscreen extent -0.9,-1 0.9,1, body extent -1.75,-0.95 1.75,0.95, height 1.8
DBV0005A-MFG [mm]
  rrect17% 1.1x0.6 smd paste+0 mask+0: 1(-1.3,0.95) 2(-1.3,0) 3(-1.3,-0.95) 4(1.3,-0.95) 5(1.3,0.95)
  silkscreen extent -2.52,-1.53 0.87,1.53, body extent -1.4,-1.45 1.4,1.45, height 1.45
DBV0005A_N [mm] "SOT23, 5-Leads, Body 2.9x1.6mm, Pitch 0.95mm, Lead Span 2.8mm, IPC Medium Density"
  rrect17% 1x0.6 smd: 1(-1.375,0.95) 2(-1.375,0) 3(-1.375,-0.95) 4(1.375,-0.95) 5(1.375,0.95)
  silkscreen extent -0.25,-1.55 0.25,1.55, body extent -1.42,-1.46 1.42,1.46, height 1.09
DDF0008A-MFG [mm]
  rrect22% 1.05x0.45 smd paste+0 mask+0: 1(-1.3,0.975) 2(-1.3,0.325) 3(-1.3,-0.325) 4(-1.3,-0.975) 5(1.3,-0.975) 6(1.3,-0.325) 7(1.3,0.325) 8(1.3,0.975)
  silkscreen extent -2.5,-1.48 0.4,1.48, body extent -1.41,-1.45 1.41,1.45, height 1.1
FCC_disclaimer [mil]
FP-M50-3900642_HDR12-MFG [mm]
  rrect9% 1.12x1.12 hole 0.65 paste-1000 mask+0: 1(-3.175,3)
  round 1.12 hole 0.65 paste-1000 mask+0: 2(-3.175,4.27) 3(-1.905,3) 4(-1.905,4.27) 5(-0.635,3) 6(-0.635,4.27) 7(0.635,3) 8(0.635,4.27) 9(1.905,3) 10(1.905,4.27) 11(3.175,3) 12(3.175,4.27)
  silkscreen extent -4.48,-0.58 4.01,3.12, body extent -4.11,-4.9 4.11,4.93, height 0.25
FP-STPS30M100DJF-TR_PowerFlat6-MFG [mm]
  rrect15% 0.65x1.25 smd paste-1000 mask+0: 1(-1.905,-2.725) 2(-0.635,-2.725) 3(0.635,-2.725) 4(1.905,-2.725)
  round 3.687 smd paste-1000 mask+0: 5(0.252,0.748)
  Top Layer region: -2.3,3.35 -1.575,3.35 -1.575,2.8 -0.95,2.8 -0.95,3.35 -0.312,3.35 -0.312,2.8 0.312,2.8 0.312,3.35 0.95,3.35 0.95,2.8 1.575,2.8 1.575,3.35 2.3,3.35 2.3,-1.3 -2.3,-1.3 -2.3,3.35
  silkscreen extent -2.7,-4.02 2.7,3.17, body extent -2.6,-3.08 2.6,3.08, height 1
IEC_HotSurface_Small [mil]
  silkscreen extent -107,-93 107,92
IHLP8787MZ [mm] "SMD, 2-Leads, Body 22x22.48mm"
  rect 5.84x18.8 smd: 1(-8.7,0) 2(8.7,0)
  silkscreen extent -11.39,-11.15 11.39,11.15, body extent -11.39,-11.15 11.39,11.15, height 13
Keystone5001 [mil] "For Keystone 500x miniature loop terminals"
  round 80 hole 40: 1(0,0)
  silkscreen extent -52,-52 52,52, body extent -49,-49 49,49, height 182
Keystone5003 [mil] "For Keystone 500x miniature loop terminals"
  round 80 hole 40: 1(0,0)
  silkscreen extent -52,-52 52,52, body extent -49,-49 49,49, height 182
Mill-Max_3620-2-32-xx-00-00-08-0 [mm] "PCB Pin, 0.04\" DIA, R/A, Edge-Mount"
  rrect3% 3.18x3.18 hole 1.65: 1(0,2.52)
  silkscreen extent -1.89,0.41 1.89,4.41, body extent -1.59,-5.06 1.59,4.11, height 0.65
Pb-Free_Overlay_Medium [mil]
  silkscreen extent -95,-95 95,95
RAQ0012B-MFG [mm]
  rrect33% 0.6x0.3 smd paste+0 mask+0: 1(-2.4,1.625) 2(-2.4,0.975) 3(-2.4,0.325) 4(-2.4,-0.325) 5(-2.4,-0.975) 6(-2.4,-1.625) 7(2.4,-1.625) 8(2.4,-0.975) 9(2.4,-0.325) 10(2.4,0.325) 11(2.4,0.975) 12(2.4,1.625)
  Top Layer region: -2.65,-1.125 -2.669,-1.121 -2.685,-1.11 -2.696,-1.094 -2.7,-1.075 -2.7,-1.075 -2.7,-0.875 -2.696,-0.856 -2.685,-0.84 -2.669,-0.829 -2.65,-0.825 -2.65,-0.825 -2.45,-0.825 -2.431,-0.821 -2.415,-0.81 -2.404,-0.794 -2.4,-0.775 -2.4,-0.775 -2.4,-0.525 -2.404,-0.506 -2.415,-0.49 -2.431,-0.479 -2.45,-0.475 -2.45,-0.475 -2.65,-0.475 -2.669,-0.471 -2.685,-0.46 -2.696,-0.444 -2.7,-0.425 -2.7,-0.425 -2.7,-0.225 -2.696,-0.206 -2.685,-0.19 -2.669,-0.179 -2.65,-0.175 -2.65,-0.175 -2.45,-0.175 -2.431,-0.171 -2.415,-0.16 -2.404,-0.144 -2.4,-0.125 -2.4,-0.125 -2.4,0.125 -2.404,0.144 -2.415,0.16 -2.431,0.171 -2.45,0.175 -2.45,0.175 -2.65,0.175 -2.675,0.182 -2.693,0.2 -2.7,0.225 -2.7,0.225 -2.7,0.425 -2.693,0.45 -2.675,0.468 -2.65,0.475 -2.65,0.475 -2.15,0.475 -2.131,0.471 -2.115,0.46 -2.104,0.444 -2.1,0.425 -2.1,0.425 -2.1,-1.075 -2.104,-1.094 -2.115,-1.11 -2.131,-1.121 -2.15,-1.125 -2.15,-1.125
  Top Layer region: 2.65,-0.475 2.675,-0.468 2.693,-0.45 2.7,-0.425 2.7,-0.425 2.7,-0.225 2.696,-0.206 2.685,-0.19 2.669,-0.179 2.65,-0.175 2.65,-0.175 2.45,-0.175 2.431,-0.171 2.415,-0.16 2.404,-0.144 2.4,-0.125 2.4,-0.125 2.4,0.125 2.404,0.144 2.415,0.16 2.431,0.171 2.45,0.175 2.45,0.175 2.65,0.175 2.675,0.182 2.693,0.2 2.7,0.225 2.7,0.225 2.7,0.425 2.696,0.444 2.685,0.46 2.669,0.471 2.65,0.475 2.65,0.475 2.45,0.475 2.431,0.479 2.415,0.49 2.404,0.506 2.4,0.525 2.4,0.525 2.4,0.775 2.404,0.794 2.415,0.81 2.431,0.821 2.45,0.825 2.45,0.825 2.65,0.825 2.669,0.829 2.685,0.84 2.696,0.856 2.7,0.875 2.7,0.875 2.7,1.075 2.693,1.1 2.675,1.118 2.65,1.125 2.65,1.125 2.15,1.125 2.131,1.121 2.115,1.11 2.104,1.094 2.1,1.075 2.1,1.075 2.1,-0.425 2.104,-0.444 2.115,-0.46 2.131,-0.471 2.15,-0.475 2.15,-0.475
  silkscreen extent -3.37,-2.05 1.73,2.55, body extent -2.5,-2 2.5,2, height 1.05
REU0008A-MFG [mm]
  rrect40% 0.6x0.25 smd paste+0 mask+0: 1(-1.4,0.75) 2(-1.4,0.25) 3(-1.4,-0.25) 4(-1.4,-0.75) 5(1.4,-0.75) 6(1.4,-0.25) 7(1.4,0.25) 8(1.4,0.75)
  silkscreen extent -2.38,-1.05 0.72,1.05, body extent -1.5,-1 1.5,1, height 1.05
SM_RADIAL_D [mm] "6.3 x 5.8mm:  Panasonic D"
  rect 3.2x1.6 smd: 1(-2.5,0) 2(2.5,0)
  silkscreen extent -3.4,-3.4 3.4,3.4, body extent -3.4,-3.4 3.4,3.4, height 6.1
VBE0015A-MFG [mm]
  round 0.265 smd paste+0 mask-1000: 1(-1.675,2.875) 11(1.675,2.875)
  rrect40% 0.7x0.25 smd paste+0 mask-1000: 2(-1.85,2.325) 3(-1.85,1.825) 4(-1.85,1.325) 5(-1.85,0.825) 8(1.85,1.325) 9(1.85,1.825) 10(1.85,2.325)
  rrect11% 1.9x3.95 smd paste-1000 mask-1000: 6(-1.3,-1.525) 7(1.3,-1.525)
  rrect40% 0.25x0.7 smd paste+0 mask-1000: 12(0.575,3.1) 13(0.075,3.1) 14(-0.425,3.1) 15(-0.925,3.1)
  Top Layer region: 2.15,2.7 2.169,2.704 2.185,2.715 2.196,2.731 2.2,2.75 2.2,2.75 2.2,2.9 2.193,2.925 2.175,2.943 2.15,2.95 2.15,2.95 1.85,2.95 1.812,2.958 1.779,2.979 1.758,3.012 1.75,3.05 1.75,3.05 1.75,3.4 1.746,3.419 1.735,3.435 1.719,3.446 1.7,3.45 1.7,3.45 1.55,3.45 1.531,3.446 1.515,3.435 1.504,3.419 1.5,3.4 1.5,3.4 1.5,2.75 1.504,2.731 1.515,2.715 1.531,2.704 1.55,2.7 1.55,2.7
  Top Layer region: -2.15,2.7 -2.169,2.704 -2.185,2.715 -2.196,2.731 -2.2,2.75 -2.2,2.75 -2.2,2.9 -2.193,2.925 -2.175,2.943 -2.15,2.95 -2.15,2.95 -1.85,2.95 -1.812,2.958 -1.779,2.979 -1.758,3.012 -1.75,3.05 -1.75,3.05 -1.75,3.4 -1.746,3.419 -1.735,3.435 -1.719,3.446 -1.7,3.45 -1.7,3.45 -1.55,3.45 -1.531,3.446 -1.515,3.435 -1.504,3.419 -1.5,3.4 -1.5,3.4 -1.5,2.75 -1.504,2.731 -1.515,2.715 -1.531,2.704 -1.55,2.7 -1.55,2.7
  silkscreen extent -2.92,-3.55 2.35,3.55, body extent -2,-3.25 2,3.25, height 0.85
WEEE_Minimum [mil] "WEEElie bin"
  silkscreen extent -95,-172 99,104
